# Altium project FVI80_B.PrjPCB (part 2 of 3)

## Sheet FVI80_Signal_DAC.SchDoc
size 431 x 279 mm; Date: Not shown in title block; ApprovedBy: Not shown in title block; CheckedBy: Not shown in title block; Author: Not shown in title block; CompanyName: Not shown in title block; Engineer: Not shown in title block; Organization: Not shown in title block; Address1: Not shown in title block; Address2: Not shown in title block; Address3: Not shown in title block; Address4: Not shown in title block; DocumentNumber: 6; Revision: Use project parameter SCH_Rev; SheetNumber: 6; SheetTotal: 11; PageSetup: Record=PageOptions¦CenterHorizontal=True¦CenterVertical=True¦PrintScale=1.00¦XCorrection=1.00¦YCorrection=1.00¦PrintKind=0¦BorderSize=5000000¦LeftOffset=0¦BottomOffset=0¦Orientation=2¦PaperLength=1000¦PaperWidth=1000¦Scale=100¦PaperSource=15¦PrintQuality=600¦MediaType=1¦DitherType=10¦PaperKind=Letter¦PrintScaleMode=1
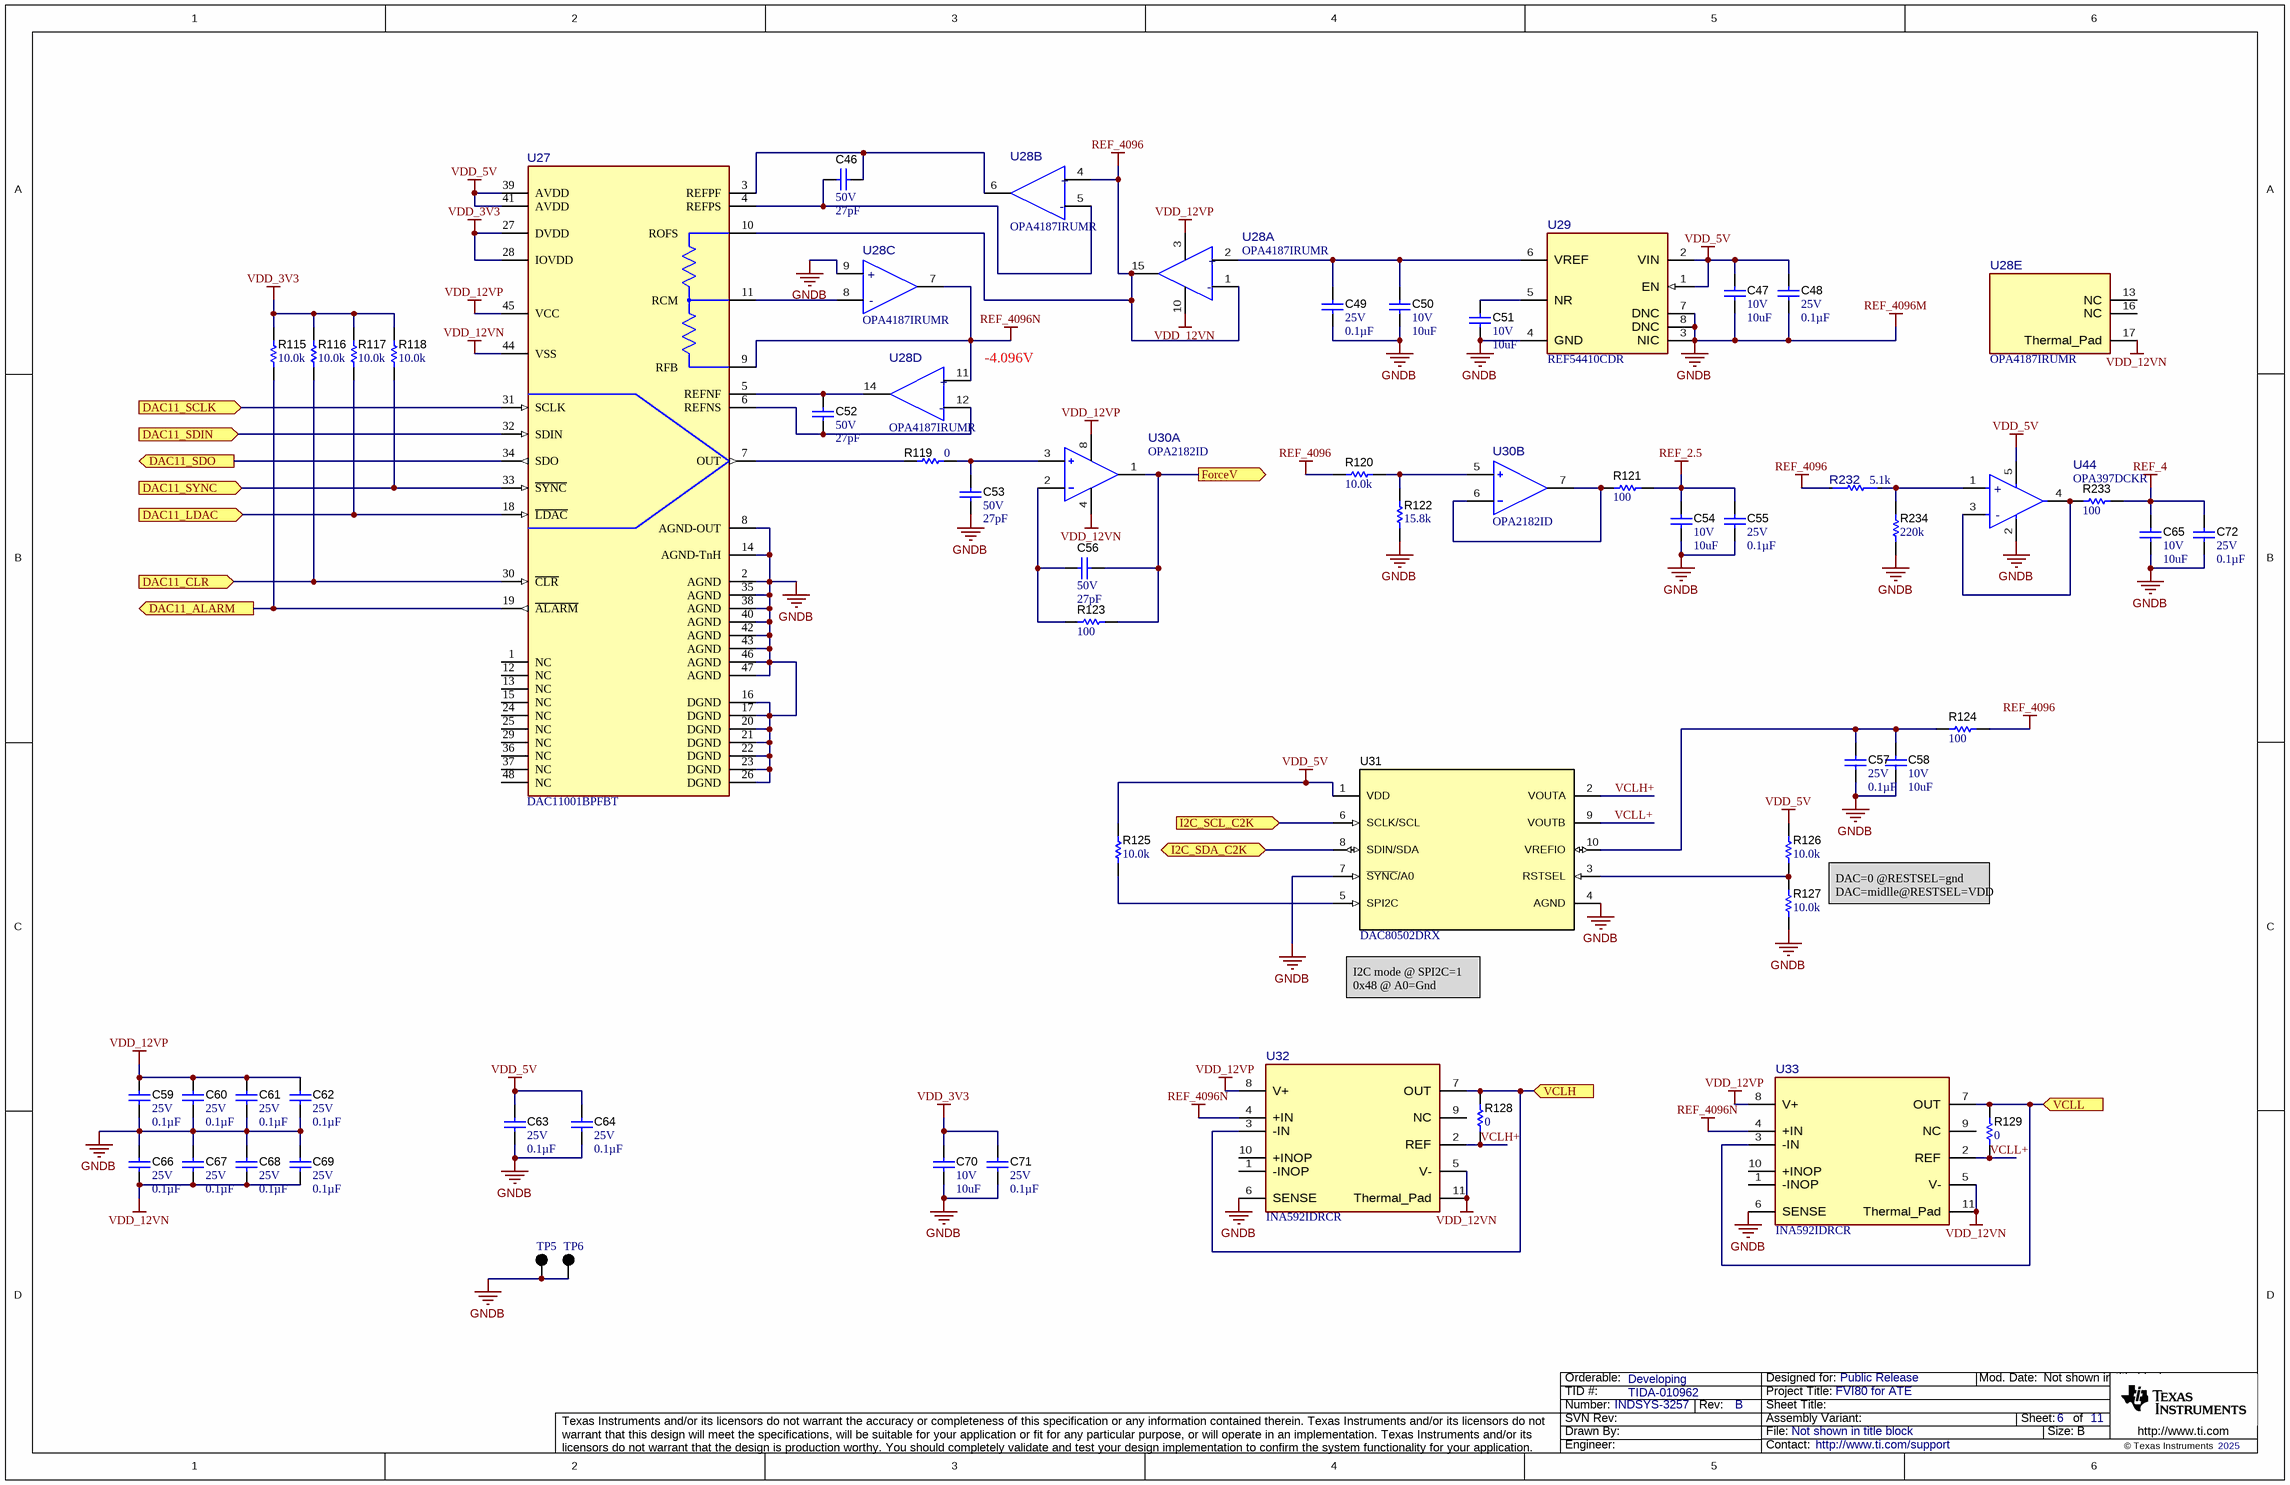
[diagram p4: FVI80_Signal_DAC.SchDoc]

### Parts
C46  VDC_V: 50V  ValueDisplayed: 27pF  [0402]  (hidden comment: GRM1555C1H270JA01D)
C47  VDC_V: 10V  ValueDisplayed: 10uF  [0402]  (hidden comment: GRM155R61A106ME11D)
C48  VDC_V: 25V  ValueDisplayed: 0.1µF  [0402]  (hidden comment: CGA2B3X7R1E104K050BB)
C49  VDC_V: 25V  ValueDisplayed: 0.1µF  [0402]  (hidden comment: CGA2B3X7R1E104K050BB)
C50  VDC_V: 10V  ValueDisplayed: 10uF  [0402]  (hidden comment: GRM155R61A106ME11D)
C51  VDC_V: 10V  ValueDisplayed: 10uF  [0402]  (hidden comment: GRM155R61A106ME11D)
C52  VDC_V: 50V  ValueDisplayed: 27pF  [0402]  (hidden comment: GRM1555C1H270JA01D)
C53  VDC_V: 50V  ValueDisplayed: 27pF  [0402]  (hidden comment: GRM1555C1H270JA01D)
C54  VDC_V: 10V  ValueDisplayed: 10uF  [0402]  (hidden comment: GRM155R61A106ME11D)
C55  VDC_V: 25V  ValueDisplayed: 0.1µF  [0402]  (hidden comment: CGA2B3X7R1E104K050BB)
C56  VDC_V: 50V  ValueDisplayed: 27pF  [0402]  (hidden comment: GRM1555C1H270JA01D)
C57  VDC_V: 25V  ValueDisplayed: 0.1µF  [0402]  (hidden comment: CGA2B3X7R1E104K050BB)
C58  VDC_V: 10V  ValueDisplayed: 10uF  [0402]  (hidden comment: GRM155R61A106ME11D)
C59  VDC_V: 25V  ValueDisplayed: 0.1µF  [0402]  (hidden comment: CGA2B3X7R1E104K050BB)
C60  VDC_V: 25V  ValueDisplayed: 0.1µF  [0402]  (hidden comment: CGA2B3X7R1E104K050BB)
C61  VDC_V: 25V  ValueDisplayed: 0.1µF  [0402]  (hidden comment: CGA2B3X7R1E104K050BB)
C62  VDC_V: 25V  ValueDisplayed: 0.1µF  [0402]  (hidden comment: CGA2B3X7R1E104K050BB)
C63  VDC_V: 25V  ValueDisplayed: 0.1µF  [0402]  (hidden comment: CGA2B3X7R1E104K050BB)
C64  VDC_V: 25V  ValueDisplayed: 0.1µF  [0402]  (hidden comment: CGA2B3X7R1E104K050BB)
C65  VDC_V: 10V  ValueDisplayed: 10uF  [0402]  (hidden comment: GRM155R61A106ME11D)
C66  VDC_V: 25V  ValueDisplayed: 0.1µF  [0402]  (hidden comment: CGA2B3X7R1E104K050BB)
C67  VDC_V: 25V  ValueDisplayed: 0.1µF  [0402]  (hidden comment: CGA2B3X7R1E104K050BB)
C68  VDC_V: 25V  ValueDisplayed: 0.1µF  [0402]  (hidden comment: CGA2B3X7R1E104K050BB)
C69  VDC_V: 25V  ValueDisplayed: 0.1µF  [0402]  (hidden comment: CGA2B3X7R1E104K050BB)
C70  VDC_V: 10V  ValueDisplayed: 10uF  [0402]  (hidden comment: GRM155R61A106ME11D)
C71  VDC_V: 25V  ValueDisplayed: 0.1µF  [0402]  (hidden comment: CGA2B3X7R1E104K050BB)
C72  VDC_V: 25V  ValueDisplayed: 0.1µF  [0402]  (hidden comment: CGA2B3X7R1E104K050BB)
R115  ValueDisplayed: 10.0k  [0402]  (hidden comment: RK73H1ETTP1002F)
R116  ValueDisplayed: 10.0k  [0402]  (hidden comment: RK73H1ETTP1002F)
R117  ValueDisplayed: 10.0k  [0402]  (hidden comment: RK73H1ETTP1002F)
R118  ValueDisplayed: 10.0k  [0402]  (hidden comment: RK73H1ETTP1002F)
R119  ValueDisplayed: 0  [0402]  (hidden comment: CRCW04020000Z0ED)
R120  ValueDisplayed: 10.0k  [0402]  (hidden comment: RK73H1ETTP1002F)
R121  ValueDisplayed: 100  [0402]  (hidden comment: RMCF0402JT100R)
R122  ValueDisplayed: 15.8k  [0402]  (hidden comment: CRCW040215K8FKED)
R123  ValueDisplayed: 100  [0402]  (hidden comment: RMCF0402JT100R)
R124  ValueDisplayed: 100  [0402]  (hidden comment: RMCF0402JT100R)
R125  ValueDisplayed: 10.0k  [0402]  (hidden comment: RK73H1ETTP1002F)
R126  ValueDisplayed: 10.0k  [0402]  (hidden comment: RK73H1ETTP1002F)
R127  ValueDisplayed: 10.0k  [0402]  (hidden comment: RK73H1ETTP1002F)
R128  ValueDisplayed: 0  [0402]  (hidden comment: CRCW04020000Z0ED)
R129  ValueDisplayed: 0  [0402]  (hidden comment: CRCW04020000Z0ED)
R232  value 5.1k  [FP-RMCF0402FT5K10_0402-MFG]  (hidden comment: RMCF0402FT5K10)
R233  ValueDisplayed: 100  [0402]  (hidden comment: RMCF0402JT100R)
R234  ValueDisplayed: 220k  [0402]  (hidden comment: RC0402FR-07220KL)
TP5  5001  [Keystone5001]  (value not drawn)
TP6  5001  [Keystone5001]  (value not drawn)
U27  DAC11001BPFBT  [PFB0048A-MFG]
U28  OPA4187IRUMR  [RUM0016B-MFG]  (parts A,B,C,D,E of 5)
U29  REF54410CDR  [D0008A-MFG]
U30  OPA2182ID  [D0008A-MFG]  (parts A,B of 2)
U31  DAC80502DRX  [DRX0010A]
U32  INA592IDRCR  [DRC0010J-MFG]
U33  INA592IDRCR  [DRC0010J-MFG]
U44  OPA397DCKR  [DCK0005A-MFG]

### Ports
DAC11_ALARM (out), DAC11_CLR (in), DAC11_LDAC (in), DAC11_SCLK (in), DAC11_SDIN (in), DAC11_SDO (out), DAC11_SYNC (in), ForceV (out), I2C_SCL_C2K (in), I2C_SDA_C2K (bidir), VCLH (in), VCLL (in)

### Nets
GNDB: C47.2 C48.1 C49.1 C50.2 C51.2 C53.1 C54.2 C55.1 C57.1 C58.2 C59.1 C60.1 C61.1 C62.1 C63.1 C64.1 C65.2 C66.2 C67.2 C68.2 C69.2 C70.2 C71.1 C72.1 R122.2 R127.1 R234.2 TP5.1 TP6.1 U27.2(AGND) U27.8(AGND-OUT) U27.14(AGND-TnH) U27.16(DGND) U27.17(DGND) U27.20(DGND) U27.21(DGND) U27.22(DGND) U27.23(DGND) U27.26(DGND) U27.35(AGND) U27.38(AGND) U27.40(AGND) U27.42(AGND) U27.43(AGND) U27.46(AGND) U27.47(AGND) U28.9(+IN_C) U29.3(NIC) U29.4(GND) U29.7(DNC) U29.8(DNC) U31.4(AGND) U31.7(~{SYNC}/A0) U32.6(SENSE) U33.6(SENSE) U44.2(V-)  [also labelled REF_4096M]
REF_2.5: C54.1 C55.2 R121.2
REF_4: C65.1 C72.2 R233.2
REF_4096: R120.2 R124.2 R232.1 U27.10(ROFS) U28.1(-IN_A) U28.4(+IN_B) U28.15(OUT_A)
REF_4096N: U27.9(RFB) U28.7(OUT_C) U28.11(+IN_D) U32.4(+IN) U33.4(+IN)
VDD_3V3: C70.1 C71.2 R115.2 R116.2 R117.2 R118.2 U27.27(DVDD) U27.28(IOVDD)
VDD_5V: C47.1 C48.2 C63.2 C64.2 R125.2 R126.2 U27.39(AVDD) U27.41(AVDD) U29.1(EN) U29.2(VIN) U31.1(VDD) U44.5(V+)
VDD_12VN: C66.1 C67.1 C68.1 C69.1 U27.44(VSS) U28.10(V-) U28.17(Thermal_Pad) U30.4(V-) U32.5(V-) U32.11(Thermal_Pad) U33.5(V-) U33.11(Thermal_Pad)
VDD_12VP: C59.2 C60.2 C61.2 C62.2 U27.45(VCC) U28.3(V+) U30.8(V+) U32.8(V+) U33.8(V+)
I2C_SCL_IN: U31.6(SCLK/SCL) ; port I2C_SCL_C2K
I2C_SDA_IN: U31.8(SDIN/SDA) ; port I2C_SDA_C2K
VCLH+: R128.1 U31.2(VOUTA) U32.2(REF)
VCLL+: R129.1 U31.9(VOUTB) U33.2(REF)
NetC46_1: C46.1 U27.3(REFPF) U28.6(OUT_B)
NetC46_2: C46.2 U27.4(REFPS) U28.5(-IN_B)
NetC49_2: C49.2 C50.1 U28.2(+IN_A) U29.6(VREF)
NetC51_1: C51.1 U29.5(NR)
NetC52_1: C52.1 U27.6(REFNS) U28.12(-IN_D)
NetC52_2: C52.2 U27.5(REFNF) U28.14(OUT_D)
NetC53_2: C53.2 R119.2 U30.3(+IN_A)
NetC56_1: C56.1 R123.2 U30.1(OUT_A) ; port ForceV
NetC56_2: C56.2 R123.1 U30.2(-IN_A)
NetC57_2: C57.2 C58.1 R124.1 U31.10(VREFIO)
NetR62_1: R129.2 U33.3(-IN) U33.7(OUT) ; port VCLL
NetR115_1: R115.1 U27.19(~{ALARM}) ; port DAC11_ALARM
NetR116_1: R116.1 U27.30(~{CLR}) ; port DAC11_CLR
NetR117_1: R117.1 U27.18(~{LDAC}) ; port DAC11_LDAC
NetR118_1: R118.1 U27.33(~{SYNC}) ; port DAC11_SYNC
NetR119_1: R119.1 U27.7(OUT)
NetR120_1: R120.1 R122.1 U30.5(+IN_B)
NetR121_1: R121.1 U30.6(-IN_B) U30.7(OUT_B)
NetR125_1: R125.1 U31.5(SPI2C)
NetR126_1: R126.1 R127.2 U31.3(RSTSEL)
NetR128_2: R128.2 U32.3(-IN) U32.7(OUT) ; port VCLH
NetR185_1: U27.32(SDIN) ; port DAC11_SDIN
NetR186_1: U27.34(SDO) ; port DAC11_SDO
NetR187_1: U27.31(SCLK) ; port DAC11_SCLK
NetR232_2: R232.2 R234.1 U44.1(+IN)
NetR233_1: R233.1 U44.3(-IN) U44.4(OUT)
NetU27_11: U27.11(RCM) U28.8(-IN_C)

Not connected (* = marked no-connect by the designer): U27 1(NC) 12(NC) 13(NC) 15(NC) 24(NC) 25(NC) 29(NC) 36(NC) 37(NC) 48(NC); U28 13(NC) 16(NC); U32 1(-INOP) 9(NC) 10(+INOP); U33 1(-INOP) 9(NC) 10(+INOP)

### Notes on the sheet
- (near U28) -4.096V
- DAC=0 @RESTSEL=gnd
  DAC=midlle@RESTSEL=VDD
- I2C mode @ SPI2C=1
  0x48 @ A0=Gnd

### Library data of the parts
C46 C52 C53 C56 = CMP-0006443-2: CAP, CERM, 27 pF, 50 V, +/- 5%, C0G/NP0, 0402; Manufacturer: MuRata; TaMin_C: -55°C; Polarized: N; SizeAreaWB_mm2: 3; Value1: Unknown; U/M: EA; Value: 27pF; TaMax_C: 125°C; SizeZ_mm: 0.6; SizeX_mm: 1; SizeY_mm: 0.5; AEC Category: Q200
C47 C50 C51 C54 C58 C65 C70 = CMP-0006564-3: CAP, CERM, 10 uF, 10 V, +/- 20%, X5R, 0402; Manufacturer: MuRata; TaMin_C: -55°C; Polarized: N; SizeAreaWB_mm2: 3; Value1: Unknown; U/M: EA; Value: 10uF; TaMax_C: 85°C; SizeZ_mm: 0.6; SizeX_mm: 1; SizeY_mm: 0.5; Cap_F: 10µF; AEC Category: Q200
C48 C49 C55 C57 C59-C64 C66-C69 C71 C72 = CMP-0080610-1: CAP, CERM, 0.1 µF, 25 V,+/- 10%, X7R, AEC-Q200 Grade 1, 0402; Manufacturer: TDK; TaMin_C: -55°C; Polarized: N; SizeAreaWB_mm2: 3; U/M: EA; Value: 0.1uF; TaMax_C: 125°C; SizeZ_mm: 0.6; SizeX_mm: 1; SizeY_mm: 0.5; AEC Qualified: Y; Cap_F: 100nF; AEC Category: Q200
R115-R118 R120 R125-R127 = CMP-0026748-1: RES, 10.0 k, 1%, 0.063 W, AEC-Q200 Grade 0, 0402; Manufacturer: KOA Speer; Power_W: 63mW; TempCo: 100 ppm/C; Value_Code: 10k0; U/M: EA; Value: 10.0k; EIA_Code: E96; Res_ohm: 10k; SizeX_mm: 1; SizeY_mm: 0.5; SizeZ_mm: 0.6; Value2: 0.063W; AEC Qualified: Y; VDC_V: 50V; AEC Grade: 0; AEC Category: Q200
R119 R128 R129 = CMP-0026822-3: RES, 0, 5%, 0.063 W, AEC-Q200 Grade 0, 0402; Manufacturer: Vishay-Dale; Value: 0; Value_Code: 0000; Power_W: 63mW; Value2: 0.063W; VDC_V: 50V; TempCo: 200 ppm/C; SizeArea_mm2: 0.5; SizeX_mm: 1; SizeZ_mm: 0.6; EIA_Code: E24; AEC Category: Q200; AEC Qualified: Y
R121 R123 R124 R233 = CMP-0026763-1: RES, 100, 1%, 0.063 W, AEC-Q200 Grade 0, 0402; Manufacturer: Stackpole Electronics Inc; Power_W: 63mW; TempCo: 100 ppm/C; Value_Code: 100R; U/M: EA; Value: 100; EIA_Code: E96; SizeX_mm: 1; SizeY_mm: 0.5; SizeZ_mm: 0.6; Value2: 0.063W; AEC Qualified: Y; AEC Grade: 0; AEC Category: Q200
R122 = CMP-0026029-3: RES, 15.8 k, 1%, 0.063 W, AEC-Q200 Grade 0, 0402; Manufacturer: Vishay-Dale; Power_W: 63mW; TempCo: 100 ppm/C; Value_Code: 15k8; Value: 15.8k; EIA_Code: E96; SizeX_mm: 1; SizeY_mm: 0.5; SizeZ_mm: 0.6; Value2: 0.063W; AEC Qualified: Y; VDC_V: 50V; AEC Category: Q200; AEC Grade: 0
R232 = CMP-0093159-1: 5.1kΩ ±1% 0.063W 0402 Thick Film Chip Resistor AEC-Q200 compliant; Manufacturer: Stackpole Electronics; Power_W: 63mW; TempCo: 100ppm/°C; SizeZ_mm: 0.35mm; AEC Qualified: Yes; VDC_V: 50V; AEC Grade: Grade 0
R234 = CMP-0026728-1: RES, 220 k, 1%, 0.0625 W, 0402; Manufacturer: Yageo America; Power_W: 62.5mW; TempCo: 100 ppm/C; U/M: EA; Value: 220k; SizeX_mm: 1; SizeY_mm: 0.5; SizeZ_mm: 0.6; AEC Qualified: N; VDC_V: 50V; AEC Category: Q200
TP5 TP6 = CMP-0055138-1: Test Point, Miniature, Black, TH; Manufacturer: Keystone; CNHeader: FALSE; Green_Lifecycle: Active; Green_REACh: Passed; ContactFinish: Silver; CT: TRUE
U27 = CMP-0093014-3: 20-Bit, Low-Noise, Ultra-Low Harmonic Distortion, FastSettling, High-Voltage Output, Digital-to-Analog Converter (DAC), TQFP48; Manufacturer: Texas Instruments; TaMin_C: -40°C; AEC Category: Q200; AEC Qualified: No; Interface: SPI; TJmax_C: +150°C; Standoff Height: 0.05mm; Number Of Channels: 1; Max Supply Voltage: 5.5V; Data Polarity: Single Ended; Resolution: 20bits; SizeZ_mm: 1.2mm; Min Supply Voltage: 1.7V; TaMax_C: +125°C; CompType: IC
U28 = CMP-0126090-1: Zero-Drift Amplifier 4 Circuit Rail-to-Rail 16-WQFN (4x4); Manufacturer: Texas Instruments; SizeZ_mm: 0.8mm; AEC Qualified: No; Gain Bandwidth: 550kHz; Input Bias Current: 100pA; Input Offset Voltage: 1uV; Max Dual Supply Voltage: 18V; Max Supply Voltage: 36V; Min Dual Supply Voltage: 2.25V; Min Supply Voltage: 4.5V; Nominal Supply Current: 100uA; Number Of Channels: 4; Output Current Per Channel: 30mA; Response Time: 48us; Standoff Height: 0mm; TaMax_C: +150°C; TaMin_C: -40°C; Voltage Gain: 160dB
U29 = CMP-0123003-1: 0.8ppm/°C drift (max), 0.11ppmp-p 1/f noise, 380μA current precision voltage reference; Manufacturer: Texas Instruments; SizeZ_mm: 1.75mm; AEC Qualified: No; Max Supply Voltage: 18V; Min Supply Voltage: 4.346V; Nominal Supply Current: 260uA; Number Of Outputs: 1; Output Type: Fixed; Output Voltage: 4.096V; Reference Type: Series; Standoff Height: 0.11mm; TaMax_C: +125°C; TaMin_C: -40°C
U30 = CMP-0096836-1: 36-V, 5-MHz, Low-Noise, Zero-Drift, MUX-Friendly, Precision Op Amps; Manufacturer: Texas Instruments; Min Supply Voltage: 4.5V; Output Current Per Channel: 65mA; Input Offset Voltage: 0.00045mV; SizeZ_mm: 1.75mm; Response Time: 3.4us; Number Of Channels: 2; Gain Bandwidth: 5MHz; Standoff Height: 0.11mm; Min Dual Supply Voltage: 2.25V; Voltage Gain: 170dB; Max Supply Voltage: 36V; AEC Qualified: No; Input Bias Current: 0.007uA; Nominal Supply Current: 0.85mA; TaMin_C: -40°C; TaMax_C: +125°C; Max Dual Supply Voltage: 18V; TJmax_C: +150°C
U31 = CMP-0860933-1: DAC80502DRX, DRX0010A (WSON-10); Alternate Manufacturer: Texas Instruments; AEC Category: Q200; SizeArea_mm2: 6.25; AEC Qualified: N; SizeAreaWB_mm2: 12.25; SizeZ_mm: 0.8; SizeY_mm: 2.5; CompType: IC
U32 U33 = CMP-0126256-1: High-precision (40µV offset), 2-MHz, 88dB CMRR, low-power, e-trim difference amplifier 10-VSON -40 to 125; Manufacturer: Texas Instruments; SizeZ_mm: 1mm; AEC Qualified: No; Bandwidth: 2MHz; Input Offset Voltage: 14uV; Max Dual Supply Voltage: 18V; Max Supply Voltage: 36V; Min Dual Supply Voltage: 2.25V; Min Supply Voltage: 4.5V; Nominal Supply Current: 1.1mA; Number Of Channels: 1; Output Current Per Channel: 65mA; Response Time: 1.3us; Standoff Height: 0mm; TaMax_C: +125°C; TaMin_C: -40°C; TJmax_C: +150°C; Voltage Gain: 1/2V/V
U44 = CMP-0126581-1: Standard (General Purpose) Amplifier 1 Circuit Push-Pull, Rail-to-Rail SC-70-5; Manufacturer: Texas Instruments; SizeZ_mm: 1.1mm; AEC Qualified: No; Gain Bandwidth: 13MHz; Input Bias Current: 0.01pA; Input Offset Voltage: 10uV; Max Dual Supply Voltage: 2.75V; Max Supply Voltage: 5.5V; Min Dual Supply Voltage: 850mV; Min Supply Voltage: 1.7V; Nominal Supply Current: 1.22mA; Number Of Channels: 1; Output Current Per Channel: 65mA; Response Time: 1us; Standoff Height: 0mm; TaMax_C: +125°C; TaMin_C: -40°C; TJmax_C: +150°C; Voltage Gain: 132dB

## Sheet FVI80_Signal_CCCV.SchDoc
size 431 x 279 mm; Date: Not shown in title block; ApprovedBy: Not shown in title block; CheckedBy: Not shown in title block; Author: Not shown in title block; CompanyName: Not shown in title block; Engineer: Not shown in title block; Organization: Not shown in title block; Address1: Not shown in title block; Address2: Not shown in title block; Address3: Not shown in title block; Address4: Not shown in title block; DocumentNumber: 4; Revision: Use project parameter SCH_Rev; SheetNumber: 4; SheetTotal: 11; PageSetup: Record=PageOptions¦CenterHorizontal=True¦CenterVertical=True¦PrintScale=1.00¦XCorrection=1.00¦YCorrection=1.00¦PrintKind=0¦BorderSize=5000000¦LeftOffset=0¦BottomOffset=0¦Orientation=2¦PaperLength=1000¦PaperWidth=1000¦Scale=100¦PaperSource=15¦PrintQuality=600¦MediaType=1¦DitherType=10¦PaperKind=Letter¦PrintScaleMode=1
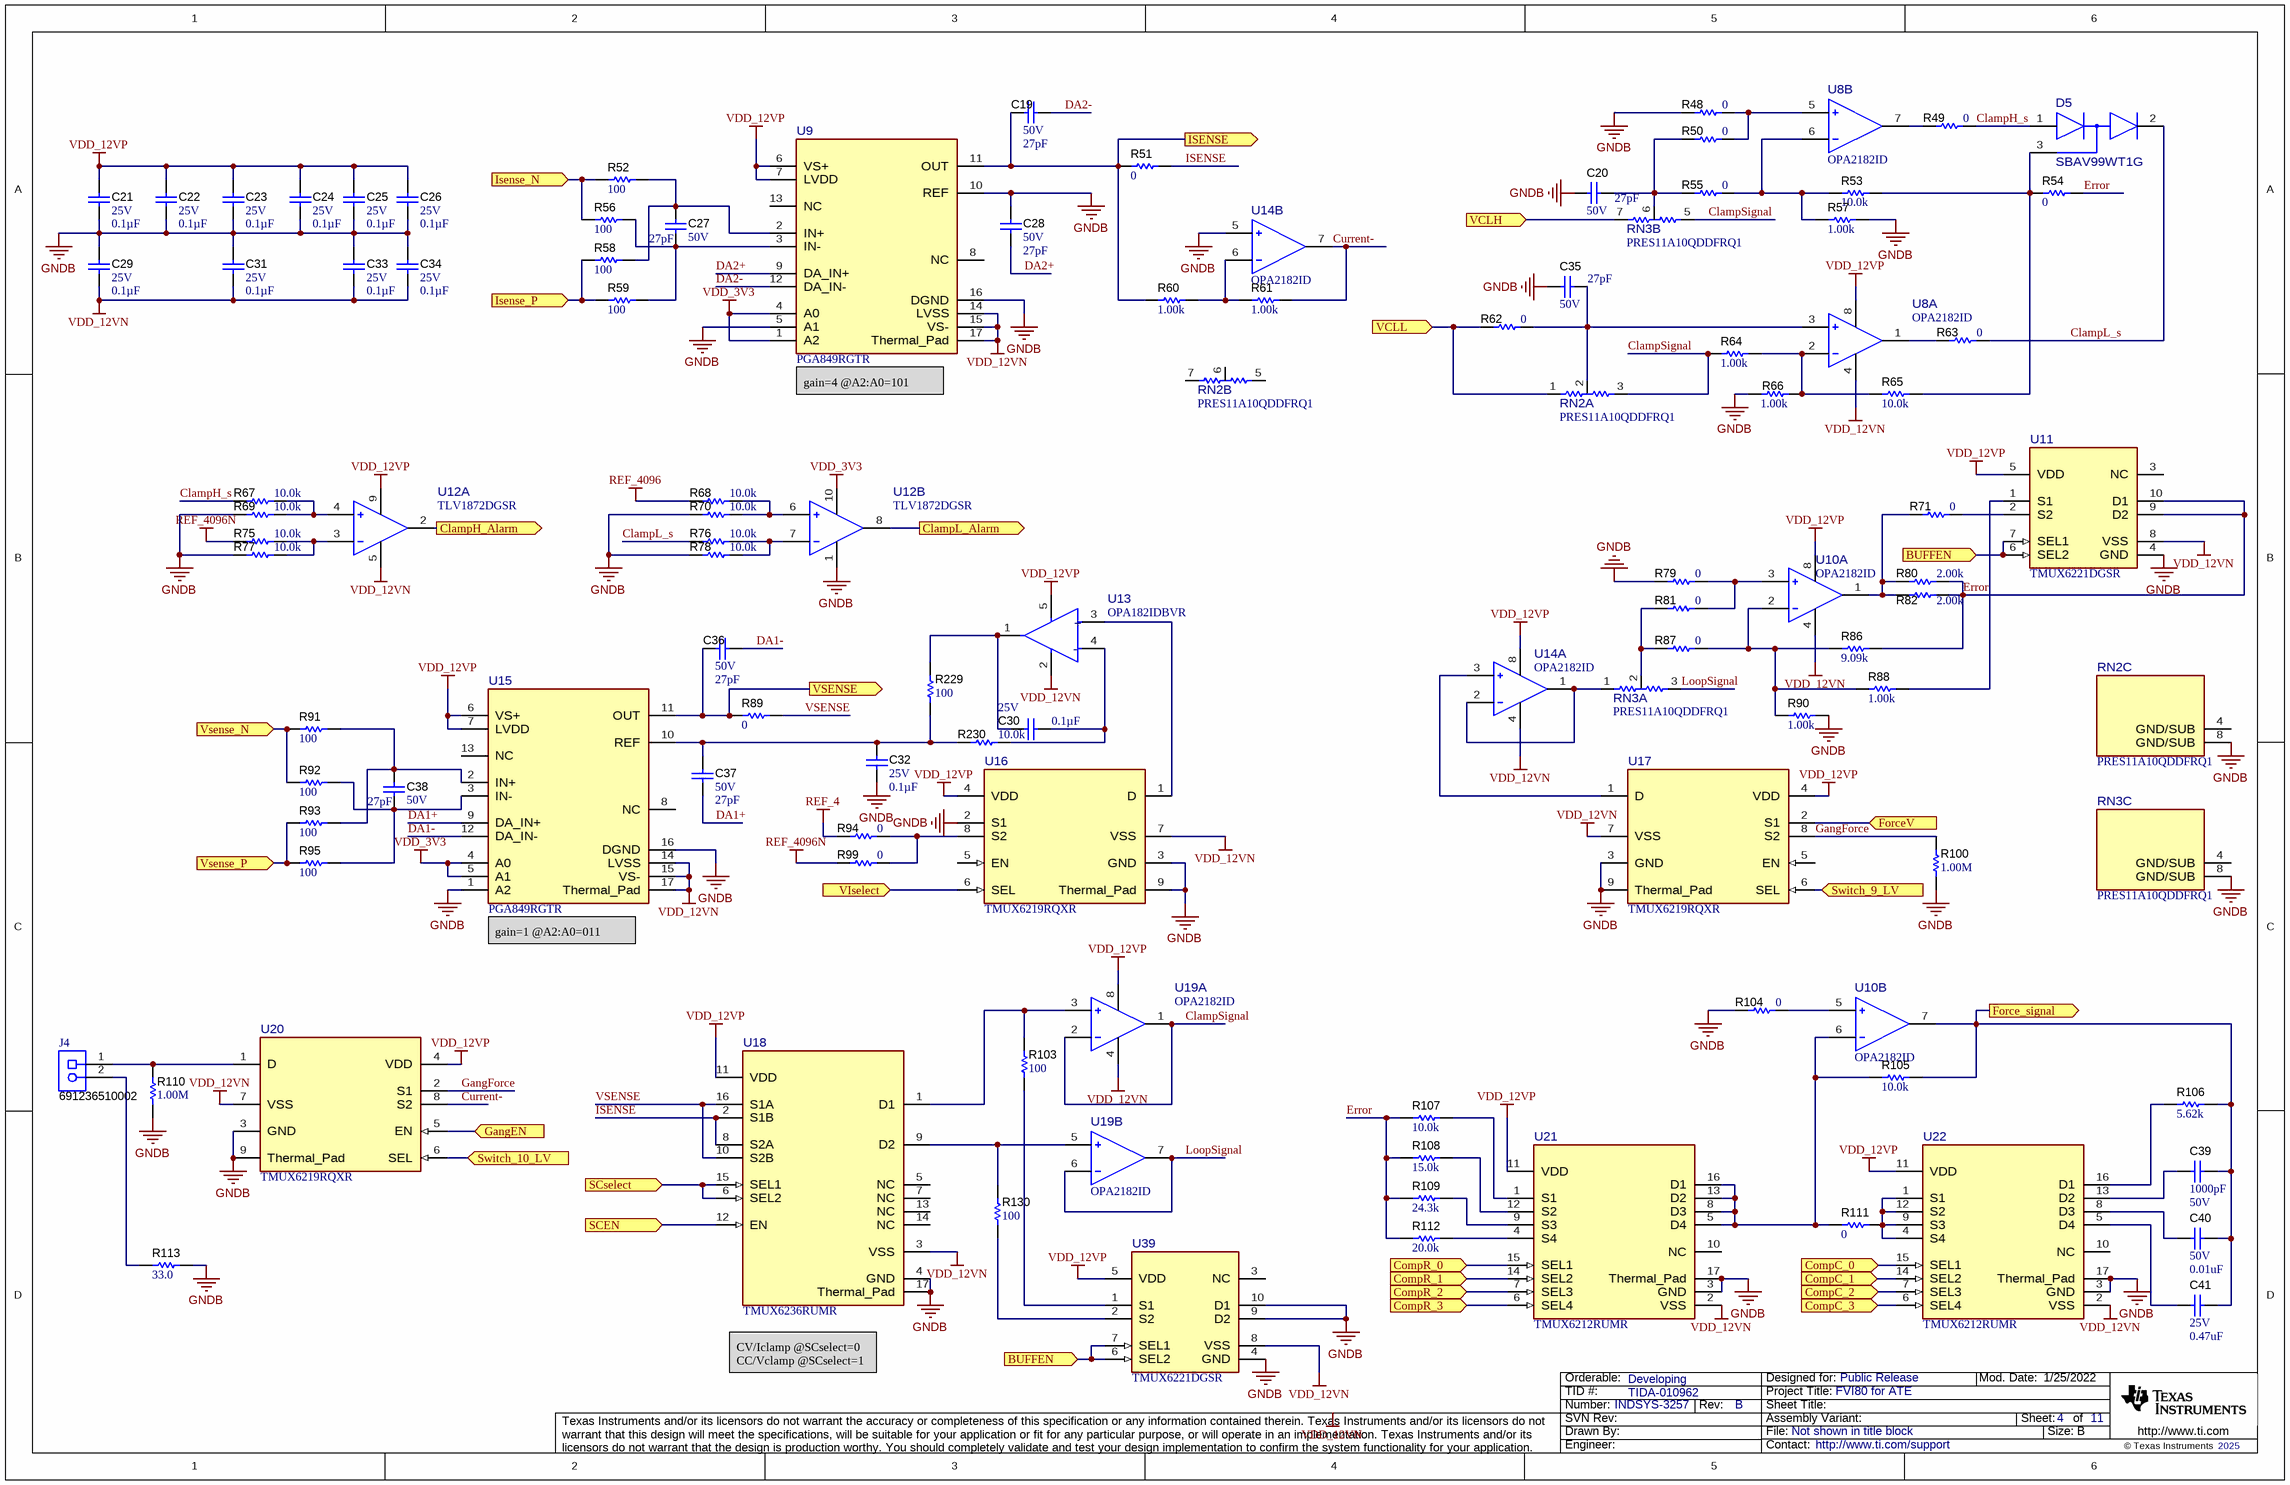
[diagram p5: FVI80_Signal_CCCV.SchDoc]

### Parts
C19  VDC_V: 50V  ValueDisplayed: 27pF  [0402]  (hidden comment: GRM1555C1H270JA01D)
C20  VDC_V: 50V  ValueDisplayed: 27pF  [0402]  (hidden comment: GRM1555C1H270JA01D)
C21  VDC_V: 25V  ValueDisplayed: 0.1µF  [0402]  (hidden comment: CGA2B3X7R1E104K050BB)
C22  VDC_V: 25V  ValueDisplayed: 0.1µF  [0402]  (hidden comment: CGA2B3X7R1E104K050BB)
C23  VDC_V: 25V  ValueDisplayed: 0.1µF  [0402]  (hidden comment: CGA2B3X7R1E104K050BB)
C24  VDC_V: 25V  ValueDisplayed: 0.1µF  [0402]  (hidden comment: CGA2B3X7R1E104K050BB)
C25  VDC_V: 25V  ValueDisplayed: 0.1µF  [0402]  (hidden comment: CGA2B3X7R1E104K050BB)
C26  VDC_V: 25V  ValueDisplayed: 0.1µF  [0402]  (hidden comment: CGA2B3X7R1E104K050BB)
C27  VDC_V: 50V  ValueDisplayed: 27pF  [0402]  (hidden comment: GRM1555C1H270JA01D)
C28  VDC_V: 50V  ValueDisplayed: 27pF  [0402]  (hidden comment: GRM1555C1H270JA01D)
C29  VDC_V: 25V  ValueDisplayed: 0.1µF  [0402]  (hidden comment: CGA2B3X7R1E104K050BB)
C30  VDC_V: 25V  ValueDisplayed: 0.1µF  [0402]  (hidden comment: CGA2B3X7R1E104K050BB)
C31  VDC_V: 25V  ValueDisplayed: 0.1µF  [0402]  (hidden comment: CGA2B3X7R1E104K050BB)
C32  VDC_V: 25V  ValueDisplayed: 0.1µF  [0402]  (hidden comment: CGA2B3X7R1E104K050BB)
C33  VDC_V: 25V  ValueDisplayed: 0.1µF  [0402]  (hidden comment: CGA2B3X7R1E104K050BB)
C34  VDC_V: 25V  ValueDisplayed: 0.1µF  [0402]  (hidden comment: CGA2B3X7R1E104K050BB)
C35  VDC_V: 50V  ValueDisplayed: 27pF  [0402]  (hidden comment: GRM1555C1H270JA01D)
C36  VDC_V: 50V  ValueDisplayed: 27pF  [0402]  (hidden comment: GRM1555C1H270JA01D)
C37  VDC_V: 50V  ValueDisplayed: 27pF  [0402]  (hidden comment: GRM1555C1H270JA01D)
C38  VDC_V: 50V  ValueDisplayed: 27pF  [0402]  (hidden comment: GRM1555C1H270JA01D)
C39  ValueDisplayed: 1000pF  VDC_V: 50V  [0402]  (hidden comment: CGA2B2X8R1H102K050BA)
C40  VDC_V: 50V  ValueDisplayed: 0.01uF  [0402]  (hidden comment: GRM155R71H103KA88D)
C41  VDC_V: 25V  ValueDisplayed: 0.47uF  [0402]  (hidden comment: GRM155R61E474KE01D)
D5  SBAV99WT1G  [FP-SBAV99WT1G_SOT-323-3-419-04-MFG]
J4  691236510002  [Wurth_691236510002]
R48  ValueDisplayed: 0  [0402]  (hidden comment: CRCW04020000Z0ED)
R49  ValueDisplayed: 0  [0402]  (hidden comment: CRCW04020000Z0ED)
R50  ValueDisplayed: 0  [0402]  (hidden comment: CRCW04020000Z0ED)
R51  ValueDisplayed: 0  [0402]  (hidden comment: CRCW04020000Z0ED)
R52  ValueDisplayed: 100  [0402]  (hidden comment: RMCF0402JT100R)
R53  ValueDisplayed: 10.0k  [0402]  (hidden comment: RK73H1ETTP1002F)
R54  ValueDisplayed: 0  [0402]  (hidden comment: CRCW04020000Z0ED)
R55  ValueDisplayed: 0  [0402]  (hidden comment: CRCW04020000Z0ED)
R56  ValueDisplayed: 100  [0402]  (hidden comment: RMCF0402JT100R)
R57  ValueDisplayed: 1.00k  [0402]  (hidden comment: CRCW04021K00FKED)
R58  ValueDisplayed: 100  [0402]  (hidden comment: RMCF0402JT100R)
R59  ValueDisplayed: 100  [0402]  (hidden comment: RMCF0402JT100R)
R60  ValueDisplayed: 1.00k  [0402]  (hidden comment: CRCW04021K00FKED)
R61  ValueDisplayed: 1.00k  [0402]  (hidden comment: CRCW04021K00FKED)
R62  ValueDisplayed: 0  [0402]  (hidden comment: CRCW04020000Z0ED)
R63  ValueDisplayed: 0  [0402]  (hidden comment: CRCW04020000Z0ED)
R64  ValueDisplayed: 1.00k  [0402]  (hidden comment: CRCW04021K00FKED)
R65  ValueDisplayed: 10.0k  [0402]  (hidden comment: RK73H1ETTP1002F)
R66  ValueDisplayed: 1.00k  [0402]  (hidden comment: CRCW04021K00FKED)
R67  ValueDisplayed: 10.0k  [0402]  (hidden comment: RK73H1ETTP1002F)
R68  ValueDisplayed: 10.0k  [0402]  (hidden comment: RK73H1ETTP1002F)
R69  ValueDisplayed: 10.0k  [0402]  (hidden comment: RK73H1ETTP1002F)
R70  ValueDisplayed: 10.0k  [0402]  (hidden comment: RK73H1ETTP1002F)
R71  ValueDisplayed: 0  [0402]  (hidden comment: CRCW04020000Z0ED)
R75  ValueDisplayed: 10.0k  [0402]  (hidden comment: RK73H1ETTP1002F)
R76  ValueDisplayed: 10.0k  [0402]  (hidden comment: RK73H1ETTP1002F)
R77  ValueDisplayed: 10.0k  [0402]  (hidden comment: RK73H1ETTP1002F)
R78  ValueDisplayed: 10.0k  [0402]  (hidden comment: RK73H1ETTP1002F)
R79  ValueDisplayed: 0  [0402]  (hidden comment: CRCW04020000Z0ED)
R80  ValueDisplayed: 2.00k  [0805_HV]  (hidden comment: ERJ-6ENF2001V)
R81  ValueDisplayed: 0  [0402]  (hidden comment: CRCW04020000Z0ED)
R82  ValueDisplayed: 2.00k  [0805_HV]  (hidden comment: ERJ-6ENF2001V)
R86  ValueDisplayed: 9.09k  [0402]  (hidden comment: CRCW04029K09FKED)
R87  ValueDisplayed: 0  [0402]  (hidden comment: CRCW04020000Z0ED)
R88  ValueDisplayed: 1.00k  [0402]  (hidden comment: CRCW04021K00FKED)
R89  ValueDisplayed: 0  [0402]  (hidden comment: CRCW04020000Z0ED)
R90  ValueDisplayed: 1.00k  [0402]  (hidden comment: CRCW04021K00FKED)
R91  ValueDisplayed: 100  [0402]  (hidden comment: RMCF0402JT100R)
R92  ValueDisplayed: 100  [0402]  (hidden comment: RMCF0402JT100R)
R93  ValueDisplayed: 100  [0402]  (hidden comment: RMCF0402JT100R)
R94  ValueDisplayed: 0  [0402]  (hidden comment: CRCW04020000Z0ED)
R95  ValueDisplayed: 100  [0402]  (hidden comment: RMCF0402JT100R)
R99  ValueDisplayed: 0  [0402]  (hidden comment: CRCW04020000Z0ED)
R100  ValueDisplayed: 1.00M  [0402]  (hidden comment: RC0402FR-071ML)
R103  ValueDisplayed: 100  [0402]  (hidden comment: RMCF0402JT100R)
R104  ValueDisplayed: 0  [0402]  (hidden comment: CRCW04020000Z0ED)
R105  ValueDisplayed: 10.0k  [0402]  (hidden comment: RK73H1ETTP1002F)
R106  ValueDisplayed: 5.62k  [0402]  (hidden comment: CRCW04025K62FKED)
R107  ValueDisplayed: 10.0k  [0402]  (hidden comment: RK73H1ETTP1002F)
R108  ValueDisplayed: 15.0k  [0402]  (hidden comment: CRCW040215K0FKED)
R109  ValueDisplayed: 24.3k  [0402]  (hidden comment: CRCW040224K3FKED)
R110  ValueDisplayed: 1.00M  [0402]  (hidden comment: RC0402FR-071ML)
R111  ValueDisplayed: 0  [0402]  (hidden comment: CRCW04020000Z0ED)
R112  ValueDisplayed: 20.0k  [0402]  (hidden comment: CRCW040220K0FKED)
R113  ValueDisplayed: 33.0  [0402]  (hidden comment: RC0402FR-0733RL)
R130  ValueDisplayed: 100  [0402]  (hidden comment: RMCF0402JT100R)
R229  ValueDisplayed: 100  [0402]  (hidden comment: RMCF0402JT100R)
R230  ValueDisplayed: 10.0k  [0402]  (hidden comment: RK73H1ETTP1002F)
RN2  PRES11A10QDDFRQ1  [DDF0008A-MFG]  (parts A,B,C of 3)
RN3  PRES11A10QDDFRQ1  [DDF0008A-MFG]  (parts A,B,C of 3)
U8  OPA2182ID  [D0008A-MFG]  (parts A,B of 2)
U9  PGA849RGTR  [RGT0016J-MFG]
U10  OPA2182ID  [D0008A-MFG]  (parts A,B of 2)
U11  TMUX6221DGSR  [DGS0010A-MFG]
U12  TLV1872DGSR  [DGS0010A-MFG]  (parts A,B of 2)
U13  OPA182IDBVR  [DBV0005A-MFG]
U14  OPA2182ID  [D0008A-MFG]  (parts A,B of 2)
U15  PGA849RGTR  [RGT0016J-MFG]
U16  TMUX6219RQXR  [RQX0008A-MFG]
U17  TMUX6219RQXR  [RQX0008A-MFG]
U18  TMUX6236RUMR  [RUM0016E-MFG]
U19  OPA2182ID  [D0008A-MFG]  (parts A,B of 2)
U20  TMUX6219RQXR  [RQX0008A-MFG]
U21  TMUX6212RUMR  [RUM0016E-MFG]
U22  TMUX6212RUMR  [RUM0016E-MFG]
U39  TMUX6221DGSR  [DGS0010A-MFG]

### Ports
BUFFEN (in), ClampH_Alarm (out), ClampL_Alarm (out), CompC_0 (in), CompC_1 (in), CompC_2 (in), CompC_3 (in), CompR_0 (in), CompR_1 (in), CompR_2 (in), CompR_3 (in), Force_signal (out), ForceV (in), GangEN (in), ISENSE (out), Isense_N (in), Isense_P (in), SCEN (in), SCselect (in), Switch_9_LV (in), Switch_10_LV (in), VCLH (in), VCLL (in), VIselect (in), VSENSE (out), Vsense_N (in), Vsense_P (in)

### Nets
GNDB: C20.1 C21.1 C22.1 C23.1 C24.1 C25.1 C26.1 C28.1 C29.2 C31.2 C32.1 C33.2 C34.2 C35.1 R48.1 R57.1 R66.2 R69.2 R70.2 R77.2 R78.2 R79.1 R90.1 R100.1 R104.1 R110.1 R113.2 RN2.8(GND/SUB) RN3.8(GND/SUB) U9.5(A1) U9.10(REF) U9.16(DGND) U11.4(GND) U12.1(VEEO) U14.5(+IN_B) U15.1(A2) U15.16(DGND) U16.2(S1) U16.3(GND) U16.9(Thermal_Pad) U17.3(GND) U17.9(Thermal_Pad) U18.4(GND) U18.17(Thermal_Pad) U20.3(GND) U20.9(Thermal_Pad) U21.3(GND) U21.17(Thermal_Pad) U22.3(GND) U22.17(Thermal_Pad) U39.4(GND) U39.9(D2) U39.10(D1)
REF_4: R94.1
REF_4096: R68.2
REF_4096N: R75.2 R99.1
VDD_3V3: U9.1(A2) U9.4(A0) U12.10(VCCO) U15.4(A0) U15.5(A1)
VDD_12VN: C29.1 C31.1 C33.1 C34.1 U8.4(V-) U9.14(LVSS) U9.15(VS-) U9.17(Thermal_Pad) U10.4(V-) U11.8(VSS) U12.5(VEEI) U13.2(V-) U14.4(V-) U15.14(LVSS) U15.15(VS-) U15.17(Thermal_Pad) U16.7(VSS) U17.7(VSS) U18.3(VSS) U19.4(V-) U20.7(VSS) U21.2(VSS) U22.2(VSS) U39.8(VSS)
VDD_12VP: C21.2 C22.2 C23.2 C24.2 C25.2 C26.2 U8.8(V+) U9.6(VS+) U9.7(LVDD) U10.8(V+) U11.5(VDD) U12.9(VCCI) U13.5(V+) U14.8(V+) U15.6(VS+) U15.7(LVDD) U16.4(VDD) U17.4(VDD) U18.11(VDD) U19.8(V+) U20.4(VDD) U21.11(VDD) U22.11(VDD) U39.5(VDD)
ClampH_s: D5.1(ANODE) R49.2 R67.2
ClampL_s: D5.2(CATHODE) R63.2 R76.2
ClampSignal: R64.2 RN2.3(RG1) RN3.5(RG2) U19.1(OUT_A) U19.2(-IN_A)
Current-: R61.1 U14.7(OUT_B) U20.8(S2)
DA1+: C37.2 U15.9(DA_IN+)
DA1-: C36.2 U15.12(DA_IN-)
DA2+: C28.2 U9.9(DA_IN+)
DA2-: C19.2 U9.12(DA_IN-)
Error: R54.2 R80.2 R82.2 R86.1 R107.1 R108.1 R109.1 R112.2 U11.9(D2) U11.10(D1)
GangForce: R100.2 U17.8(S2) U20.2(S1)
ISENSE: R51.2 U18.2(S1B) U18.8(S2A)
LoopSignal: RN3.3(RG1) U19.6(-IN_B) U19.7(OUT_B)
VSENSE: R89.2 U18.10(S2B) U18.16(S1A)
NetC19_1: C19.1 R51.1 R60.2 U9.11(OUT) ; port ISENSE
NetC20_2: C20.2 R50.1 R55.1 RN3.6(RMID2)
NetC27_1: C27.1 R52.2 R58.2 U9.2(IN+)
NetC27_2: C27.2 R56.2 R59.2 U9.3(IN-)
NetC30_1: C30.1 R230.2 U13.4(-IN)
NetC30_2: C30.2 R229.2 U13.1(OUT)
NetC32_2: C32.2 C37.1 R229.1 R230.1 U15.10(REF)
NetC35_2: C35.2 R62.2 RN2.2(RMID1) U8.3(+IN_A)
NetC36_1: C36.1 R89.1 U15.11(OUT) ; port VSENSE
NetC38_1: C38.1 R91.2 R93.2 U15.2(IN+)
NetC38_2: C38.2 R92.2 R95.2 U15.3(IN-)
NetC39_1: C39.1 U22.13(D2)
NetC39_2: C39.2 C40.2 C41.2 R105.2 R106.2 U10.7(OUT_B) ; port Force_signal
NetC40_1: C40.1 U22.8(D3)
NetC41_1: C41.1 U22.5(D4)
NetC56_1: U17.2(S1) ; port ForceV
NetD5_3: D5.3(CATHODE/ANODE) R53.2 R54.1 R65.2
NetJ4_1: J4.1 R110.2 U20.1(D)
NetJ4_2: J4.2 R113.1
NetR48_2: R48.2 R50.2 U8.5(+IN_B)
NetR49_1: R49.1 U8.7(OUT_B)
NetR52_1: R52.1 R56.1 ; port Isense_N
NetR53_1: R53.1 R55.2 R57.2 U8.6(-IN_B)
NetR58_1: R58.1 R59.1 ; port Isense_P
NetR60_1: R60.1 R61.2 U14.6(-IN_B)
NetR62_1: R62.1 RN2.1(RIN1) ; port VCLL
NetR63_1: R63.1 U8.1(OUT_A)
NetR64_1: R64.1 R65.1 R66.1 U8.2(-IN_A)
NetR67_1: R67.1 R69.1 U12.4(IN1+)
NetR68_1: R68.1 R70.1 U12.6(IN2+)
NetR71_1: R71.1 R80.1 R82.1 U10.1(OUT_A)
NetR71_2: R71.2 U11.2(S2)
NetR75_1: R75.1 R77.1 U12.3(IN1-)
NetR76_1: R76.1 R78.1 U12.7(IN2-)
NetR79_2: R79.2 R81.2 U10.3(+IN_A)
NetR81_1: R81.1 R87.1 RN3.2(RMID1)
NetR86_2: R86.2 R87.2 R88.2 R90.2 U10.2(-IN_A)
NetR88_1: R88.1 U11.1(S1)
NetR91_1: R91.1 R92.1 ; port Vsense_N
NetR93_1: R93.1 R95.1 ; port Vsense_P
NetR94_2: R94.2 R99.2 U16.8(S2)
NetR103_1: R103.1 U18.1(D1) U19.3(+IN_A)
NetR103_2: R103.2 U39.1(S1)
NetR104_2: R104.2 U10.5(+IN_B)
NetR105_1: R105.1 R111.1 U10.6(-IN_B) U21.5(D4) U21.8(D3) U21.13(D2) U21.16(D1)
NetR106_1: R106.1 U22.16(D1)
NetR107_2: R107.2 U21.1(S1)
NetR108_2: R108.2 U21.12(S2)
NetR109_2: R109.2 U21.9(S3)
NetR111_2: R111.2 U22.1(S1) U22.4(S4) U22.9(S3) U22.12(S2)
NetR112_1: R112.1 U21.4(S4)
NetR128_2: RN3.7(RIN2) ; port VCLH
NetR130_1: R130.1 U18.9(D2) U19.5(+IN_B)
NetR130_2: R130.2 U39.2(S2)
NetR165_2: U12.2(OUT1) ; port ClampH_Alarm
NetR166_2: U12.8(OUT2) ; port ClampL_Alarm
NetRN3_1: RN3.1(RIN1) U14.1(OUT_A) U14.2(-IN_A)
NetU11_6: U11.6(SEL2) U11.7(SEL1) U39.6(SEL2) U39.7(SEL1) ; port BUFFEN
NetU13_3: U13.3(+IN) U16.1(D)
NetU14_3: U14.3(+IN_A) U17.1(D)
NetU16_6: U16.6(SEL) ; port VIselect
NetU17_6: U17.6(SEL) ; port Switch_9_LV
NetU18_6: U18.6(SEL2) U18.15(SEL1) ; port SCselect
NetU18_12: U18.12(EN) ; port SCEN
NetU20_5: U20.5(EN) ; port GangEN
NetU20_6: U20.6(SEL) ; port Switch_10_LV
NetU21_6: U21.6(SEL4) ; port CompR_3
NetU21_7: U21.7(SEL3) ; port CompR_2
NetU21_14: U21.14(SEL2) ; port CompR_1
NetU21_15: U21.15(SEL1) ; port CompR_0
NetU22_6: U22.6(SEL4) ; port CompC_3
NetU22_7: U22.7(SEL3) ; port CompC_2
NetU22_14: U22.14(SEL2) ; port CompC_1
NetU22_15: U22.15(SEL1) ; port CompC_0

Not connected (* = marked no-connect by the designer): RN2 4(GND/SUB) 5(RG2) 6(RMID2) 7(RIN2); RN3 4(GND/SUB); U9 8(NC) 13(NC); U11 3(NC); U15 8(NC) 13(NC); U16 5(EN); U17 5(EN); U18 5(NC) 7(NC) 13(NC) 14(NC); U21 10(NC); U22 10(NC); U39 3(NC)

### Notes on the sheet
- (near U9) gain=4 @A2:A0=101
- (near U15) gain=1 @A2:A0=011
- (near U18) CV/Iclamp @SCselect=0
  CC/Vclamp @SCselect=1
- Labels drawn without touching a wire or pin: VDD_12VN

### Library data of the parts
C19 C20 C27 C28 C35-C38 = CMP-0006443-2: as C46 on sheet FVI80_Signal_DAC
C21-C26 C29-C34 = CMP-0080610-1: as C48 on sheet FVI80_Signal_DAC
C39 = CMP-0860997-1: CAP, CERM, 1000 pF, 50 V,+/- 10%, X8R, AEC-Q200 Grade 0, 0402; Manufacturer: TDK; SizeArea_mm2: 0.5; U/M: EA; SizeX_mm: 1; Polarized: N; AEC Grade: 0; AEC Qualified: Y; TaMin_C: -55°C; Value: 1000pF; TaMax_C: 150°C; SizeZ_mm: 0.6; Cap_F: 1nF; SizeAreaWB_mm2: 3; AEC Category: Q200
C40 = CMP-0006674-2: CAP, CERM, 0.01 uF, 50 V, +/- 10%, X7R, 0402; Manufacturer: MuRata; TaMin_C: -55°C; Polarized: N; SizeAreaWB_mm2: 3; Value1: Unknown; U/M: EA; Value: 0.01uF; TaMax_C: 125°C; SizeZ_mm: 0.6; SizeX_mm: 1; SizeY_mm: 0.5; Cap_F: 10nF; AEC Category: Q200
C41 = CMP-0064928-2: CAP, CERM, 0.47 uF, 25 V,+/- 10%, X5R, 0402; Manufacturer: MuRata; TaMin_C: -55°C; Polarized: N; SizeAreaWB_mm2: 3; Value1: Unknown; U/M: EA; Value: 0.47uF; TaMax_C: 85°C; SizeZ_mm: 0.6; SizeX_mm: 1; SizeY_mm: 0.5; Cap_F: 470nF; AEC Category: Q200
D5 = CMP-0089118-1: Diode Array 1 Pair Series Connection Standard 100V 215mA Surface Mount SC-70, SOT-323; Manufacturer: On Semiconductor; TJmax_C: 150°C; SizeZ_mm: 1mm; Peak Reverse Current: 1uA; Cap_F: 1.5pF; Max Surge Forward Current: 0.5A; Standoff Height: 0mm; Ciiva Ids: 812969; AEC Grade: Grade 0; Import Ts: 1521844614; AEC Qualified: Yes
J4 = CMP-0079044-1: Terminal Block, 5.08mm, 2x1, R/A, TH; Manufacturer: Wurth Elektronik; Pitch_mm: 5.08; Cert_VDE: Y; Gender: Female; Voltage_V: 300V; Current_A: 20A; Row_Count: 1
R48-R51 R54 R55 R62 R63 R71 R79 R81 R87 R89 R94 R99 R104 = CMP-0026822-3: as R119 on sheet FVI80_Signal_DAC
R52 R56 R58 R59 R91-R93 R95 R229 = CMP-0026763-1: as R121 on sheet FVI80_Signal_DAC
R53 R65 R105 R107 R230 = CMP-0026748-1: as R115-R118 on sheet FVI80_Signal_DAC
R57 R60 R61 R64 R66 R88 R90 = CMP-0026071-2: RES, 1.00 k, 1%, 0.063 W, 0402; Manufacturer: Vishay-Dale; Power_W: 63mW; TempCo: 100 ppm/C; Value_Code: 1k00; U/M: EA; Value: 1.00k; EIA_Code: E96; Res_ohm: 1k; SizeX_mm: 1; SizeY_mm: 0.5; SizeZ_mm: 0.6; Value2: 0.063W; VDC_V: 50V; AEC Category: Q200
R67-R70 R75-R78 = CMP-0026748-1: RES, 10.0 k, 1%, 0.063 W, AEC-Q200 Grade 0, 0402; Manufacturer: KOA Speer; Power_W: 63mW; TempCo: 100 ppm/C; Value_Code: 10k0; U/M: EA; Value: 10.0k; EIA_Code: E96; Res_ohm: 10k; SizeX_mm: 1; SizeY_mm: 0.5; SizeZ_mm: 0.6; Value2: 0.063W; AEC Qualified: Y; VDC_V: 50V; AEC Category: Q200; AEC Grade: 0
R80 R82 = CMP-0021613-3: RES, 2.00 k, 1%, 0.125 W, AEC-Q200 Grade 0, 0805; Manufacturer: Panasonic; Power_W: 125mW; TempCo: 100 ppm/C; Value_Code: 2k00; Value: 2.00k; EIA_Code: E96; Res_ohm: 2k; SizeX_mm: 2; SizeY_mm: 1.25; SizeZ_mm: 1.45; Value2: 0.125W; SizeArea_mm2: 2.5; AEC Qualified: Y; AEC Category: Q200; AEC Grade: 0; SizeAreaWB_mm2: 6.75
R86 = CMP-0026619-3: RES, 9.09 k, 1%, 0.063 W, AEC-Q200 Grade 0, 0402; Manufacturer: Vishay-Dale; Power_W: 63mW; TempCo: 100 ppm/C; Value_Code: 9k09; Value: 9.09k; EIA_Code: E96; SizeX_mm: 1; SizeY_mm: 0.5; SizeZ_mm: 0.6; Value2: 0.063W; AEC Qualified: Y; VDC_V: 50V; AEC Category: Q200; AEC Grade: 0
R100 R110 = CMP-0026727-1: RES, 1.00 M, 1%, 0.063 W, 0402; Manufacturer: Yageo America; Power_W: 63mW; TempCo: 100 ppm/C; Value_Code: 1M00; U/M: EA; Value: 1.00Meg; EIA_Code: E96; Res_ohm: 1M; SizeX_mm: 1; SizeY_mm: 0.5; SizeZ_mm: 0.6; Value2: 0.063W; AEC Category: Q200
R103 R130 = CMP-0026763-1: RES, 100, 1%, 0.063 W, AEC-Q200 Grade 0, 0402; Manufacturer: Stackpole Electronics Inc; Power_W: 63mW; TempCo: 100 ppm/C; Value_Code: 100R; U/M: EA; Value: 100; EIA_Code: E96; SizeX_mm: 1; SizeY_mm: 0.5; SizeZ_mm: 0.6; Value2: 0.063W; AEC Qualified: Y; AEC Category: Q200; AEC Grade: 0
R106 = CMP-0026467-2: RES, 5.62 k, 1%, 0.063 W, AEC-Q200 Grade 0, 0402; Manufacturer: Vishay-Dale; Power_W: 63mW; TempCo: 100 ppm/C; Value_Code: 5k62; Value: 5.62k; EIA_Code: E96; SizeX_mm: 1; SizeY_mm: 0.5; SizeZ_mm: 0.6; Value2: 0.063W; AEC Qualified: Y; VDC_V: 50V; AEC Category: Q200; AEC Grade: 0
R108 = CMP-0026027-3: RES, 15.0 k, 1%, 0.063 W, AEC-Q200 Grade 0, 0402; Manufacturer: Vishay-Dale; Power_W: 63mW; TempCo: 100 ppm/C; Value_Code: 15k0; Value: 15.0k; EIA_Code: E96; Res_ohm: 15k; SizeX_mm: 1; SizeY_mm: 0.5; SizeZ_mm: 0.6; Value2: 0.063W; AEC Qualified: Y; VDC_V: 50V; AEC Category: Q200; AEC Grade: 0
R109 = CMP-0026195-2: RES, 24.3 k, 1%, 0.063 W, AEC-Q200 Grade 0, 0402; Manufacturer: Vishay-Dale; Power_W: 63mW; TempCo: 100 ppm/C; Value_Code: 24k3; Value: 24.3k; EIA_Code: E96; SizeX_mm: 1; SizeY_mm: 0.5; SizeZ_mm: 0.6; Value2: 0.063W; AEC Qualified: Y; VDC_V: 50V; AEC Category: Q200; AEC Grade: 0
R111 = CMP-0026822-3: RES, 0, 5%, 0.063 W, AEC-Q200 Grade 0, 0402; Manufacturer: Vishay-Dale; Power_W: 63mW; TempCo: 200 ppm/C; Value_Code: 0000; Value: 0; EIA_Code: E24; SizeX_mm: 1; SizeY_mm: 0.5; SizeZ_mm: 0.6; Value2: 0.063W; AEC Qualified: Y; AEC Category: Q200; VDC_V: 50V
R112 = CMP-0026162-2: RES, 20.0 k, 1%, 0.063 W, AEC-Q200 Grade 0, 0402; Manufacturer: Vishay-Dale; Power_W: 63mW; TempCo: 100 ppm/C; Value_Code: 20k0; Value: 20.0k; EIA_Code: E96; Res_ohm: 20k; SizeX_mm: 1; SizeY_mm: 0.5; SizeZ_mm: 0.6; Value2: 0.063W; AEC Qualified: Y; VDC_V: 50V; AEC Category: Q200; AEC Grade: 0
R113 = CMP-0026732-1: RES, 33.0, 1%, 0.062 W, 0402; Manufacturer: Yageo America; Power_W: 62mW; TempCo: 100 ppm/C; Value_Code: 33R0; U/M: EA; Value: 33.0; Res_ohm: 33; SizeX_mm: 1; SizeY_mm: 0.5; SizeZ_mm: 0.6; Value2: 0.062W; AEC Qualified: N; AEC Category: Q200; VDC_V: 50V
RN2 RN3 = CMP-0123029-1: Automotive low-noise matched thin-film resistor divider network with 1kΩ fixed input 8-SOT-23-THIN -40 to 125; Manufacturer: Texas Instruments; SizeZ_mm: 1.1mm; AEC Qualified: Yes; AEC Grade: Grade 1; Number Of Resistors: 4; Standoff Height: 0mm; TaMax_C: +125°C; TaMin_C: -40°C; TempCo: 18ppm/°C; TJmax_C: +150°C; Tolerance_%: 2%
U8 U10 U14 U19 = CMP-0096836-1: as U30 on sheet FVI80_Signal_DAC
U9 U15 = CMP-0120565-1: Low-Noise, Wide-Bandwidth, Precision Programmable Gain Instrumentation Amplifier; Manufacturer: Texas Instruments; SizeZ_mm: 1mm; AEC Qualified: No; Bandwidth: 10MHz; Input Bias Current: 0.0005uA; Input Offset Voltage: 0.015mV; Max Dual Supply Voltage: 18V; Max Supply Voltage: 36V; Min Dual Supply Voltage: 4V; Min Supply Voltage: 8V; Nominal Supply Current: 3mA; Number Of Channels: 1; Output Current Per Channel: 45mA; Response Time: 0.95us; Standoff Height: 0mm; TaMax_C: +125°C; TaMin_C: -40°C; TJmax_C: +150°C; Voltage Gain: 0.000125-0.016V/mV
U11 U39 = CMP-0126280-1: 36-V, latch-up immune, 1: 1 (SPST) 2 channel precision switch with 1.8V logic (active high) 10-VSSOP -40 to 125; Manufacturer: Texas Instruments; SizeZ_mm: 1.1mm; AEC Qualified: No; -3Db Bandwith: 67MHz; Max Supply Voltage: 36V; Min Supply Voltage: 4.5V; Mux Demux Ratio: 1:1; On State Resistance: 2.1Ω; PositionCount: 2; Standoff Height: 0.05mm; TaMax_C: +125°C; TaMin_C: -40°C; TJmax_C: +150°C
U12 = CMP-0121034-1: 36 V High-Speed Comparators with Separate Input and Output Supplies; Manufacturer: Texas Instruments; SizeZ_mm: 1.1mm; AEC Qualified: No; Input Bias Current: 0.0005uA; Input Offset Voltage: 0.5mV; Max Supply Voltage: 36V; Min Supply Voltage: 2.7V; Nominal Supply Current: 70-95uA; Number Of Channels: 2; Output Current Per Channel: 30mA; Standoff Height: 0.05mm; TaMax_C: +125°C; TaMin_C: -40°C; TJmax_C: +150°C
U13 = CMP-0126339-1: Zero-Drift Amplifier 1 Circuit Rail-to-Rail SOT-23-5; Manufacturer: Texas Instruments; SizeZ_mm: 1.45mm; AEC Qualified: No; Gain Bandwidth: 5MHz; Input Bias Current: 50pA; Input Offset Voltage: 0.45uV; Max Dual Supply Voltage: 36V; Max Supply Voltage: 18V; Min Dual Supply Voltage: 2.25V; Min Supply Voltage: 4.5V; Nominal Supply Current: 0.85mA; Number Of Channels: 1; Output Current Per Channel: 65mA; Response Time: 3.4us; Standoff Height: 0mm; TaMax_C: +125°C; TaMin_C: -40°C; TJmax_C: +150°C; Voltage Gain: 170dB
U16 U17 U20 = CMP-0126080-1: 36-V low Ron 2: 1 one channel multiplexer with 1.8-V logic control 8-WSON -40 to 125; Manufacturer: Texas Instruments; SizeZ_mm: 0.8mm; AEC Qualified: No; -3Db Bandwith: 43MHz; Max Supply Voltage: 36V; Min Supply Voltage: 4.5V; Mux Demux Ratio: 2:1; Nominal Supply Current: 30uA; On State Resistance: 2.1Ω; PositionCount: 1; Standoff Height: 0mm; TaMax_C: +125°C; TaMin_C: -40°C; TJmax_C: +150°C
U18 = CMP-0123006-1: 36-V, low-RON, 2: 1 (SPDT) two-channel precision switch with latch-up immunity and 1.8-V logic 16-WQFN -40 to 125; Manufacturer: Texas Instruments; SizeZ_mm: 0.8mm; AEC Qualified: No; -3Db Bandwith: 55MHz; Max Supply Voltage: 36V; Min Supply Voltage: 4.5V; Mux Demux Ratio: 2:1; On State Resistance: 2Ω; PositionCount: 2; Standoff Height: 0mm; TaMax_C: +125°C; TaMin_C: -40°C; TJmax_C: +150°C
U21 U22 = CMP-0122930-1: 36-V low RON, 1: 1, four-channel, multiplexer with 1.8-V logic control 16-WQFN -40 to 125; Manufacturer: Texas Instruments; SizeZ_mm: 0.8mm; AEC Qualified: No; -3Db Bandwith: 135MHz; Max Supply Voltage: 36V; Min Supply Voltage: 4.5V; Mux Demux Ratio: 1:1; On State Resistance: 2Ω; PositionCount: 4; Standoff Height: 0mm; TaMax_C: +125°C; TaMin_C: -40°C; TJmax_C: +150°C

## Sheet FVI80_C2000_Connector.SchDoc
size 431 x 279 mm; Date: Not shown in title block; ApprovedBy: Not shown in title block; CheckedBy: Not shown in title block; Author: Not shown in title block; CompanyName: Not shown in title block; Engineer: Not shown in title block; Organization: Not shown in title block; Address1: Not shown in title block; Address2: Not shown in title block; Address3: Not shown in title block; Address4: Not shown in title block; DocumentNumber: 9; Revision: Use project parameter SCH_Rev; SheetNumber: 9; SheetTotal: 11; PageSetup: Record=PageOptions¦CenterHorizontal=True¦CenterVertical=True¦PrintScale=1.00¦XCorrection=1.00¦YCorrection=1.00¦PrintKind=0¦BorderSize=5000000¦LeftOffset=0¦BottomOffset=0¦Orientation=2¦PaperLength=1000¦PaperWidth=1000¦Scale=100¦PaperSource=15¦PrintQuality=600¦MediaType=1¦DitherType=10¦PaperKind=Letter¦PrintScaleMode=1
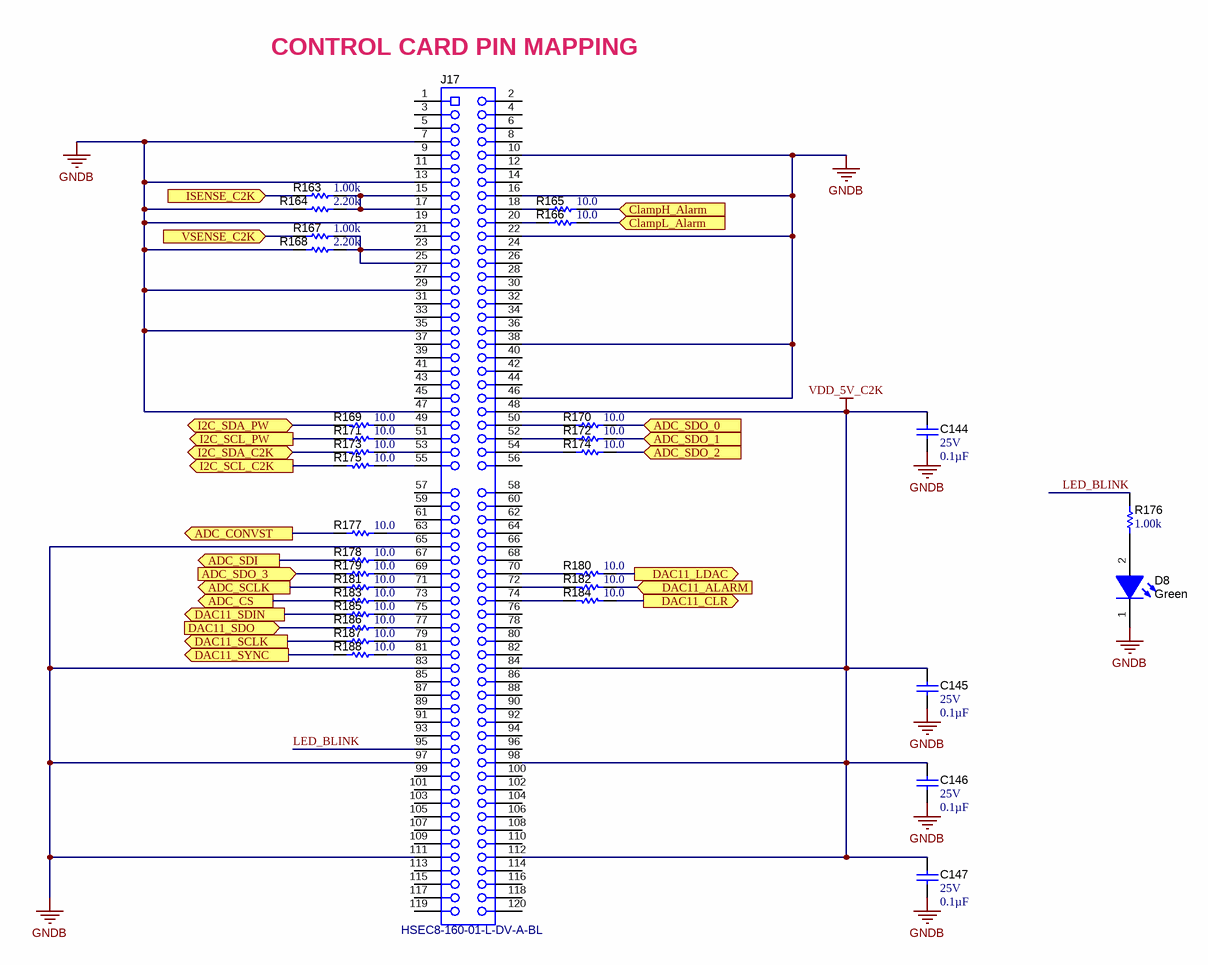
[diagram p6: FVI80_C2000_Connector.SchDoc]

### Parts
C144  VDC_V: 25V  ValueDisplayed: 0.1µF  [0402]  (hidden comment: CGA2B3X7R1E104K050BB)
C145  VDC_V: 25V  ValueDisplayed: 0.1µF  [0402]  (hidden comment: CGA2B3X7R1E104K050BB)
C146  VDC_V: 25V  ValueDisplayed: 0.1µF  [0402]  (hidden comment: CGA2B3X7R1E104K050BB)
C147  VDC_V: 25V  ValueDisplayed: 0.1µF  [0402]  (hidden comment: CGA2B3X7R1E104K050BB)
D8  value Green  [WL-SMCW_GREEN]  (hidden comment: 150060VS75000)
J17  HSEC8-160-01-L-DV-A-BL  [controlCARD-120HSEC]
R163  ValueDisplayed: 1.00k  [0402]  (hidden comment: CRCW04021K00FKED)
R164  ValueDisplayed: 2.20k  [0402]  (hidden comment: CRCW04022K20FKED)
R165  ValueDisplayed: 10.0  [0402]  (hidden comment: MCR01MZPF10R0)
R166  ValueDisplayed: 10.0  [0402]  (hidden comment: MCR01MZPF10R0)
R167  ValueDisplayed: 1.00k  [0402]  (hidden comment: CRCW04021K00FKED)
R168  ValueDisplayed: 2.20k  [0402]  (hidden comment: CRCW04022K20FKED)
R169  ValueDisplayed: 10.0  [0402]  (hidden comment: MCR01MZPF10R0)
R170  ValueDisplayed: 10.0  [0402]  (hidden comment: MCR01MZPF10R0)
R171  ValueDisplayed: 10.0  [0402]  (hidden comment: MCR01MZPF10R0)
R172  ValueDisplayed: 10.0  [0402]  (hidden comment: MCR01MZPF10R0)
R173  ValueDisplayed: 10.0  [0402]  (hidden comment: MCR01MZPF10R0)
R174  ValueDisplayed: 10.0  [0402]  (hidden comment: MCR01MZPF10R0)
R175  ValueDisplayed: 10.0  [0402]  (hidden comment: MCR01MZPF10R0)
R176  ValueDisplayed: 1.00k  [0402]  (hidden comment: CRCW04021K00FKED)
R177  ValueDisplayed: 10.0  [0402]  (hidden comment: MCR01MZPF10R0)
R178  ValueDisplayed: 10.0  [0402]  (hidden comment: MCR01MZPF10R0)
R179  ValueDisplayed: 10.0  [0402]  (hidden comment: MCR01MZPF10R0)
R180  ValueDisplayed: 10.0  [0402]  (hidden comment: MCR01MZPF10R0)
R181  ValueDisplayed: 10.0  [0402]  (hidden comment: MCR01MZPF10R0)
R182  ValueDisplayed: 10.0  [0402]  (hidden comment: MCR01MZPF10R0)
R183  ValueDisplayed: 10.0  [0402]  (hidden comment: MCR01MZPF10R0)
R184  ValueDisplayed: 10.0  [0402]  (hidden comment: MCR01MZPF10R0)
R185  ValueDisplayed: 10.0  [0402]  (hidden comment: MCR01MZPF10R0)
R186  ValueDisplayed: 10.0  [0402]  (hidden comment: MCR01MZPF10R0)
R187  ValueDisplayed: 10.0  [0402]  (hidden comment: MCR01MZPF10R0)
R188  ValueDisplayed: 10.0  [0402]  (hidden comment: MCR01MZPF10R0)

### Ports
ADC_CONVST (out), ADC_CS (out), ADC_SCLK (out), ADC_SDI (out), ADC_SDO_0 (in), ADC_SDO_1 (in), ADC_SDO_2 (in), ADC_SDO_3 (in), ClampH_Alarm (in), ClampL_Alarm (in), DAC11_ALARM (in), DAC11_CLR (out), DAC11_LDAC (out), DAC11_SCLK (out), DAC11_SDIN (out), DAC11_SDO (in), DAC11_SYNC (out), I2C_SCL_C2K (out), I2C_SCL_PW (out), I2C_SDA_C2K (bidir), I2C_SDA_PW (bidir), ISENSE_C2K (in), VSENSE_C2K (in)

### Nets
GNDB: C144.1 C145.1 C146.1 C147.1 D8.1(K) J17.7 J17.10 J17.13 J17.16 J17.19 J17.22 J17.29 J17.35 J17.38 J17.46 J17.47 J17.65 J17.83 J17.97 J17.111 R164.1 R168.1
VDD_5V_C2K: C144.2 C145.2 C146.2 C147.2 J17.48 J17.84 J17.98 J17.112
I2C_SCL_IN: R175.1 ; port I2C_SCL_C2K
I2C_SDA_IN: R173.1 ; port I2C_SDA_C2K
LED_BLINK: J17.95 R176.1
NetD8_2: D8.2(A) R176.2
NetJ17_15: J17.15 J17.17 R163.1 R164.2
NetJ17_18: J17.18 R165.1
NetJ17_20: J17.20 R166.1
NetJ17_23: J17.23 J17.25 R167.1 R168.2
NetJ17_49: J17.49 R169.2
NetJ17_50: J17.50 R170.1
NetJ17_51: J17.51 R171.2
NetJ17_52: J17.52 R172.1
NetJ17_53: J17.53 R173.2
NetJ17_54: J17.54 R174.1
NetJ17_55: J17.55 R175.2
NetJ17_63: J17.63 R177.2
NetJ17_67: J17.67 R178.2
NetJ17_69: J17.69 R179.2
NetJ17_70: J17.70 R180.2
NetJ17_71: J17.71 R181.2
NetJ17_72: J17.72 R182.2
NetJ17_73: J17.73 R183.2
NetJ17_74: J17.74 R184.2
NetJ17_75: J17.75 R185.2
NetJ17_77: J17.77 R186.2
NetJ17_79: J17.79 R187.2
NetJ17_81: J17.81 R188.2
NetR115_1: R182.1 ; port DAC11_ALARM
NetR116_1: R184.1 ; port DAC11_CLR
NetR117_1: R180.1 ; port DAC11_LDAC
NetR118_1: R188.1 ; port DAC11_SYNC
NetR134_1: R177.1 ; port ADC_CONVST
NetR134_2: R183.1 ; port ADC_CS
NetR163_2: R163.2 ; port ISENSE_C2K
NetR165_2: R165.2 ; port ClampH_Alarm
NetR166_2: R166.2 ; port ClampL_Alarm
NetR167_2: R167.2 ; port VSENSE_C2K
NetR169_1: R169.1 ; port I2C_SDA_PW
NetR170_2: R170.2 ; port ADC_SDO_0
NetR171_1: R171.1 ; port I2C_SCL_PW
NetR172_2: R172.2 ; port ADC_SDO_1
NetR174_2: R174.2 ; port ADC_SDO_2
NetR178_1: R178.1 ; port ADC_SDI
NetR179_1: R179.1 ; port ADC_SDO_3
NetR181_1: R181.1 ; port ADC_SCLK
NetR185_1: R185.1 ; port DAC11_SDIN
NetR186_1: R186.1 ; port DAC11_SDO
NetR187_1: R187.1 ; port DAC11_SCLK

Not connected (* = marked no-connect by the designer): J17 1 2 3 4 5 6 8 9 11 12 14 21 24 26 27 28 30 31 32 33 34 36 37 39 40 41 42 43 44 45 56 57 58 59 60 61 62 64 66 68 76 78 80 82 85 86 87 88 89 90 91 92 93 94 96 99 100 101 102 103 104 105 106 107 108 109 110 113 114 115 116 117 118 119 120

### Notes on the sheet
- (near J17) CONTROL CARD PIN MAPPING

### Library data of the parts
C144-C147 = CMP-0080610-1: as C48 on sheet FVI80_Signal_DAC
D8 = CMP-0002894-2: LED, Green, SMD; Manufacturer: Wurth Elektronik; Type: AlInGaP; Vf_V: 2V; Io_A: 20mA; Value1: W
J17 = CMP-0003814-2: C2000 controlCARD-120HSEC connector, SMT; Manufacturer: Samtec; Note: The pin numbering does not match Samtec datasheet
R163 R167 R176 = CMP-0026071-2: as R57 on sheet FVI80_Signal_CCCV
R164 R168 = CMP-0026231-2: RES, 2.20 k, 1%, 0.063 W, AEC-Q200 Grade 0, 0402; Manufacturer: Vishay-Dale; Power_W: 63mW; TempCo: 100 ppm/C; Value_Code: 2k20; Value: 2.20k; Res_ohm: 2.2k; SizeX_mm: 1; SizeY_mm: 0.5; SizeZ_mm: 0.6; Value2: 0.063W; AEC Qualified: Y; AEC Category: Q200; AEC Grade: 0
R165 R166 R169-R175 R177-R188 = CMP-0025963-3: RES, 10.0, 1%, 0.063 W, AEC-Q200 Grade 0, 0402; Manufacturer: Vishay-Dale; PartNumber: CRCW040210R0FKED; Power_W: 63mW; TempCo: 100 ppm/C; Value_Code: 10R0; Value: 10.0; EIA_Code: E96; Res_ohm: 10; SizeX_mm: 1; SizeY_mm: 0.5; SizeZ_mm: 0.6; Value2: 0.063W; AEC Qualified: Y; VDC_V: 50V; AEC Category: Q200; AEC Grade: 0

## Sheet FVI80_MUX_Signal.SchDoc
size 431 x 279 mm; Date: Not shown in title block; ApprovedBy: Not shown in title block; CheckedBy: Not shown in title block; Author: Not shown in title block; CompanyName: Not shown in title block; Engineer: Not shown in title block; Organization: Not shown in title block; Address1: Not shown in title block; Address2: Not shown in title block; Address3: Not shown in title block; Address4: Not shown in title block; DocumentNumber: 5; Revision: Use project parameter SCH_Rev; SheetNumber: 5; SheetTotal: 11; PageSetup: Record=PageOptions¦CenterHorizontal=True¦CenterVertical=True¦PrintScale=1.00¦XCorrection=1.00¦YCorrection=1.00¦PrintKind=0¦BorderSize=5000000¦LeftOffset=0¦BottomOffset=0¦Orientation=2¦PaperLength=1000¦PaperWidth=1000¦Scale=100¦PaperSource=15¦PrintQuality=600¦MediaType=1¦DitherType=10¦PaperKind=Letter¦PrintScaleMode=1
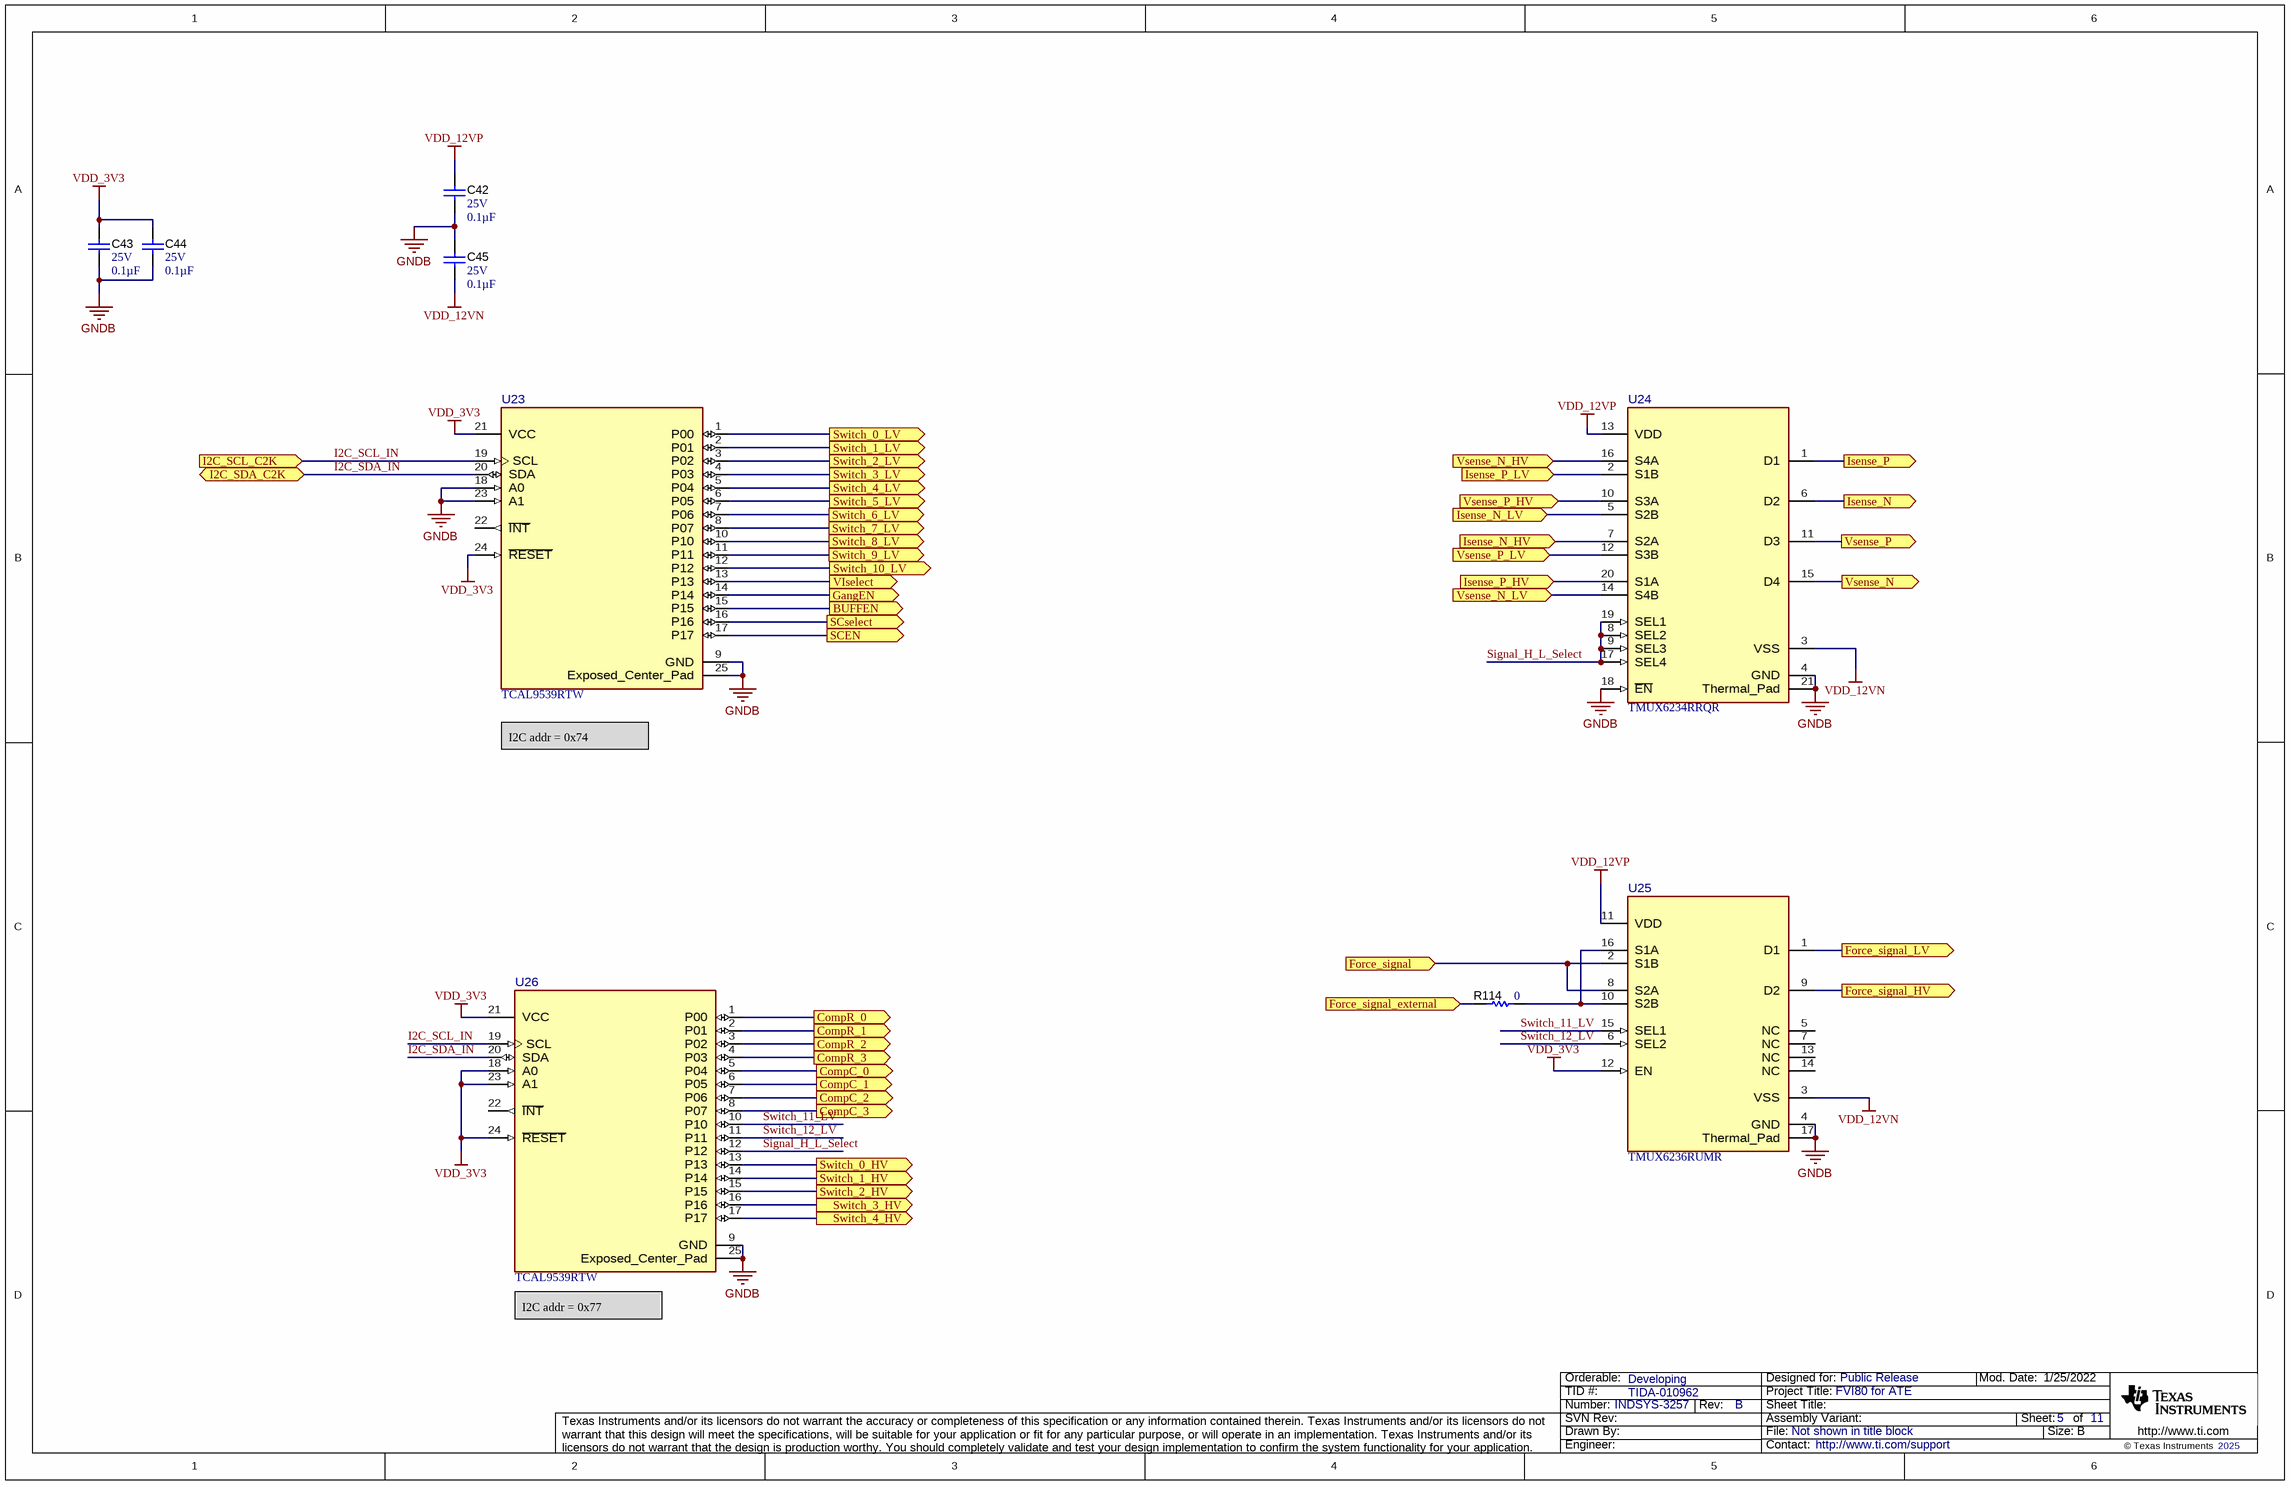
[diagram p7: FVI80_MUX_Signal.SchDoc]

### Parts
C42  VDC_V: 25V  ValueDisplayed: 0.1µF  [0402]  (hidden comment: CGA2B3X7R1E104K050BB)
C43  VDC_V: 25V  ValueDisplayed: 0.1µF  [0402]  (hidden comment: CGA2B3X7R1E104K050BB)
C44  VDC_V: 25V  ValueDisplayed: 0.1µF  [0402]  (hidden comment: CGA2B3X7R1E104K050BB)
C45  VDC_V: 25V  ValueDisplayed: 0.1µF  [0402]  (hidden comment: CGA2B3X7R1E104K050BB)
R114  ValueDisplayed: 0  [0402]  (hidden comment: CRCW04020000Z0ED)
U23  TCAL9539RTW  [RTW0024B-MFG]
U24  TMUX6234RRQR  [RRQ0020A-MFG]
U25  TMUX6236RUMR  [RUM0016E-MFG]
U26  TCAL9539RTW  [RTW0024B-MFG]

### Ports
BUFFEN (out), CompC_0 (out), CompC_1 (out), CompC_2 (out), CompC_3 (out), CompR_0 (out), CompR_1 (out), CompR_2 (out), CompR_3 (out), Force_signal (in), Force_signal_external (in), Force_signal_HV (out), Force_signal_LV (out), GangEN (out), I2C_SCL_C2K (in), I2C_SDA_C2K (bidir), Isense_N (out), Isense_N_HV (in), Isense_N_LV (in), Isense_P (out), Isense_P_HV (in), Isense_P_LV (in), SCEN (out), SCselect (out), Switch_0_HV (out), Switch_0_LV (out), Switch_1_HV (out), Switch_1_LV (out), Switch_2_HV (out), Switch_2_LV (out), Switch_3_HV (out), Switch_3_LV (out), Switch_4_HV (out), Switch_4_LV (out), Switch_5_LV (out), Switch_6_LV (out), Switch_7_LV (out), Switch_8_LV (out), Switch_9_LV (out), Switch_10_LV (out), VIselect (out), Vsense_N (out), Vsense_N_HV (in), Vsense_N_LV (in), Vsense_P (out), Vsense_P_HV (in), Vsense_P_LV (in)

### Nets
GNDB: C42.1 C43.1 C44.1 C45.2 U23.9(GND) U23.18(A0) U23.23(A1) U23.25(Exposed_Center_Pad) U24.4(GND) U24.18(~{EN}) U24.21(Thermal_Pad) U25.4(GND) U25.17(Thermal_Pad) U26.9(GND) U26.25(Exposed_Center_Pad)
VDD_3V3: C43.2 C44.2 U23.21(VCC) U23.24(~{RESET}) U25.12(EN) U26.18(A0) U26.21(VCC) U26.23(A1) U26.24(~{RESET})
VDD_12VN: C45.1 U24.3(VSS) U25.3(VSS)
VDD_12VP: C42.2 U24.13(VDD) U25.11(VDD)
I2C_SCL_IN: U23.19(SCL) U26.19(SCL) ; port I2C_SCL_C2K
I2C_SDA_IN: U23.20(SDA) U26.20(SDA) ; port I2C_SDA_C2K
Signal_H_L_Select: U24.8(SEL2) U24.9(SEL3) U24.17(SEL4) U24.19(SEL1) U26.12(P12)
Switch_11_LV: U25.15(SEL1) U26.10(P10)
Switch_12_LV: U25.6(SEL2) U26.11(P11)
NetC39_2: U25.2(S1B) U25.8(S2A) ; port Force_signal
NetD1_2: U24.5(S2B) ; port Isense_N_LV
NetD2_2: U24.2(S1B) ; port Isense_P_LV
NetD3_2: U24.12(S3B) ; port Vsense_P_LV
NetD4_1: U24.14(S4B) ; port Vsense_N_LV
NetK1_2: U23.3(P02) ; port Switch_2_LV
NetK2_2: U23.1(P00) ; port Switch_0_LV
NetK3_2: U23.2(P01) ; port Switch_1_LV
NetK4_2: U23.4(P03) ; port Switch_3_LV
NetK5_2: U23.5(P04) ; port Switch_4_LV
NetK6_2: U23.6(P05) ; port Switch_5_LV
NetK7_2: U23.7(P06) ; port Switch_6_LV
NetK8_2: U23.10(P10) ; port Switch_8_LV
NetK9_2: U23.8(P07) ; port Switch_7_LV
NetR3_1: U25.1(D1) ; port Force_signal_LV
NetR52_1: U24.6(D2) ; port Isense_N
NetR58_1: U24.1(D1) ; port Isense_P
NetR91_1: U24.15(D4) ; port Vsense_N
NetR93_1: U24.11(D3) ; port Vsense_P
NetR114_1: R114.1 ; port Force_signal_external
NetR114_2: R114.2 U25.10(S2B) U25.16(S1A)
NetR197_2: U26.13(P13) ; port Switch_0_HV
NetR199_2: U26.14(P14) ; port Switch_1_HV
NetR200_1: U24.20(S1A) ; port Isense_P_HV
NetR201_2: U26.15(P15) ; port Switch_2_HV
NetR202_1: U24.7(S2A) ; port Isense_N_HV
NetR203_2: U26.16(P16) ; port Switch_3_HV
NetR205_1: U24.10(S3A) ; port Vsense_P_HV
NetR206_2: U26.17(P17) ; port Switch_4_HV
NetR207_1: U24.16(S4A) ; port Vsense_N_HV
NetR209_1: U25.9(D2) ; port Force_signal_HV
NetU11_6: U23.15(P15) ; port BUFFEN
NetU16_6: U23.13(P13) ; port VIselect
NetU17_6: U23.11(P11) ; port Switch_9_LV
NetU18_6: U23.16(P16) ; port SCselect
NetU18_12: U23.17(P17) ; port SCEN
NetU20_5: U23.14(P14) ; port GangEN
NetU20_6: U23.12(P12) ; port Switch_10_LV
NetU21_6: U26.4(P03) ; port CompR_3
NetU21_7: U26.3(P02) ; port CompR_2
NetU21_14: U26.2(P01) ; port CompR_1
NetU21_15: U26.1(P00) ; port CompR_0
NetU22_6: U26.8(P07) ; port CompC_3
NetU22_7: U26.7(P06) ; port CompC_2
NetU22_14: U26.6(P05) ; port CompC_1
NetU22_15: U26.5(P04) ; port CompC_0

Not connected (* = marked no-connect by the designer): U23 22(~{INT}); U25 5(NC) 7(NC) 13(NC) 14(NC); U26 22(~{INT})

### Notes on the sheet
- (near U23) I2C addr = 0x74
- (near U26) I2C addr = 0x77

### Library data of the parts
C42-C45 = CMP-0080610-1: as C48 on sheet FVI80_Signal_DAC
R114 = CMP-0026822-3: as R119 on sheet FVI80_Signal_DAC
U23 U26 = CMP-0094311-1: Low-Voltage Translating, 16-Bit I2C-Bus, SMBus I/O Expander with Interrupt Output, Reset, and Agile I/O Configuration Registers; Manufacturer: Texas Instruments; TaMax_C: +125°C; AEC Qualified: No; Max Supply Voltage: 3.6V; Min Supply Voltage: 1.08V; SizeZ_mm: 0.8mm; Interface: I2C,SMBus; Nominal Supply Current: 2-11uA; Frequency_Fixed: 1MHz; Standoff Height: 0mm; Number Of I/Os: 16; TaMin_C: -40°C
U24 = CMP-0120407-1: 36 V, Low Ron, 2:1, 4 Channel Precision Switches with 1.8 V Logic; Manufacturer: Texas Instruments; SizeZ_mm: 0.8mm; AEC Qualified: No; -3Db Bandwith: 95MHz; Max Supply Voltage: 36V; Min Supply Voltage: 4.5V; Nominal Supply Current: 65uA; On State Resistance: 3.6Ω; PositionCount: 4; Standoff Height: 0mm; TaMax_C: +125°C; TaMin_C: -40°C; TJmax_C: +150°C
U25 = CMP-0123006-1: as U18 on sheet FVI80_Signal_CCCV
